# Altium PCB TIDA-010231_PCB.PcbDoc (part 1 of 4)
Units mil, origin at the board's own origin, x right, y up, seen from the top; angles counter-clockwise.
Board outline 3937.01 x 3740.16 mil, 4 copper layers (Top Layer, Signal Layer 1, Signal Layer 2, Bottom Layer), stack 65.355 mil thick; 295 components, 163 nets, 818 pads, 213 vias.
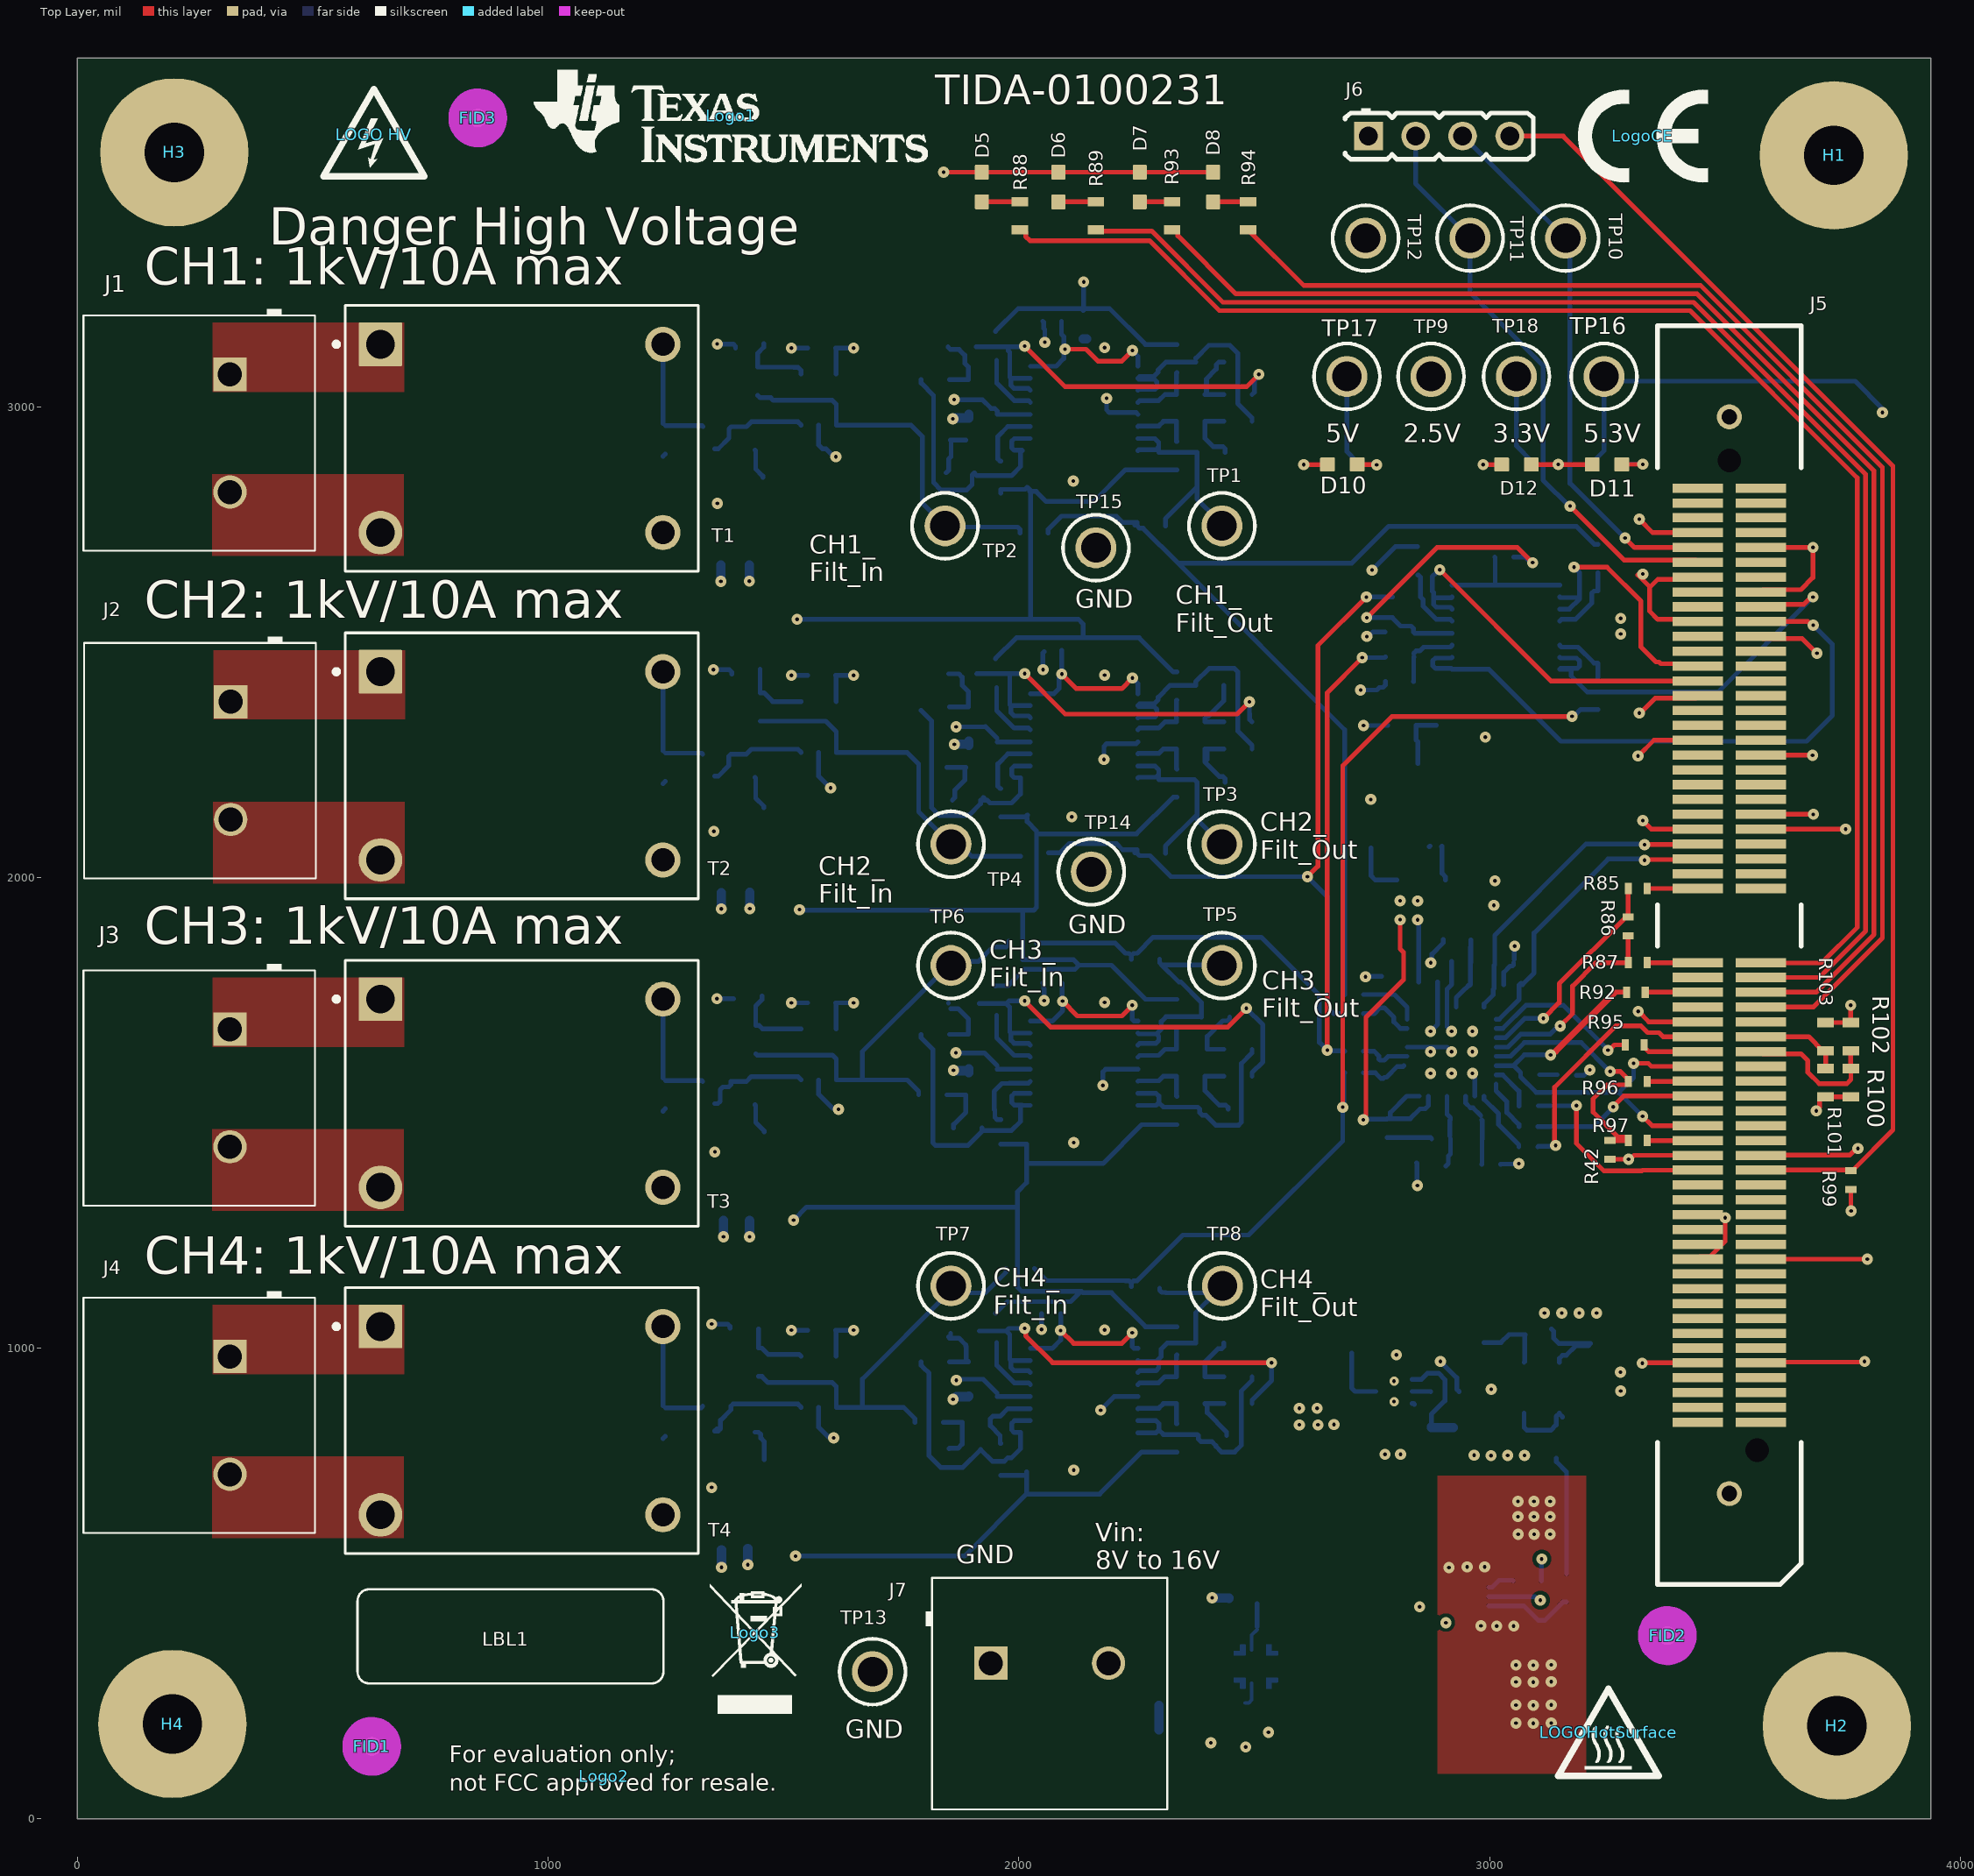
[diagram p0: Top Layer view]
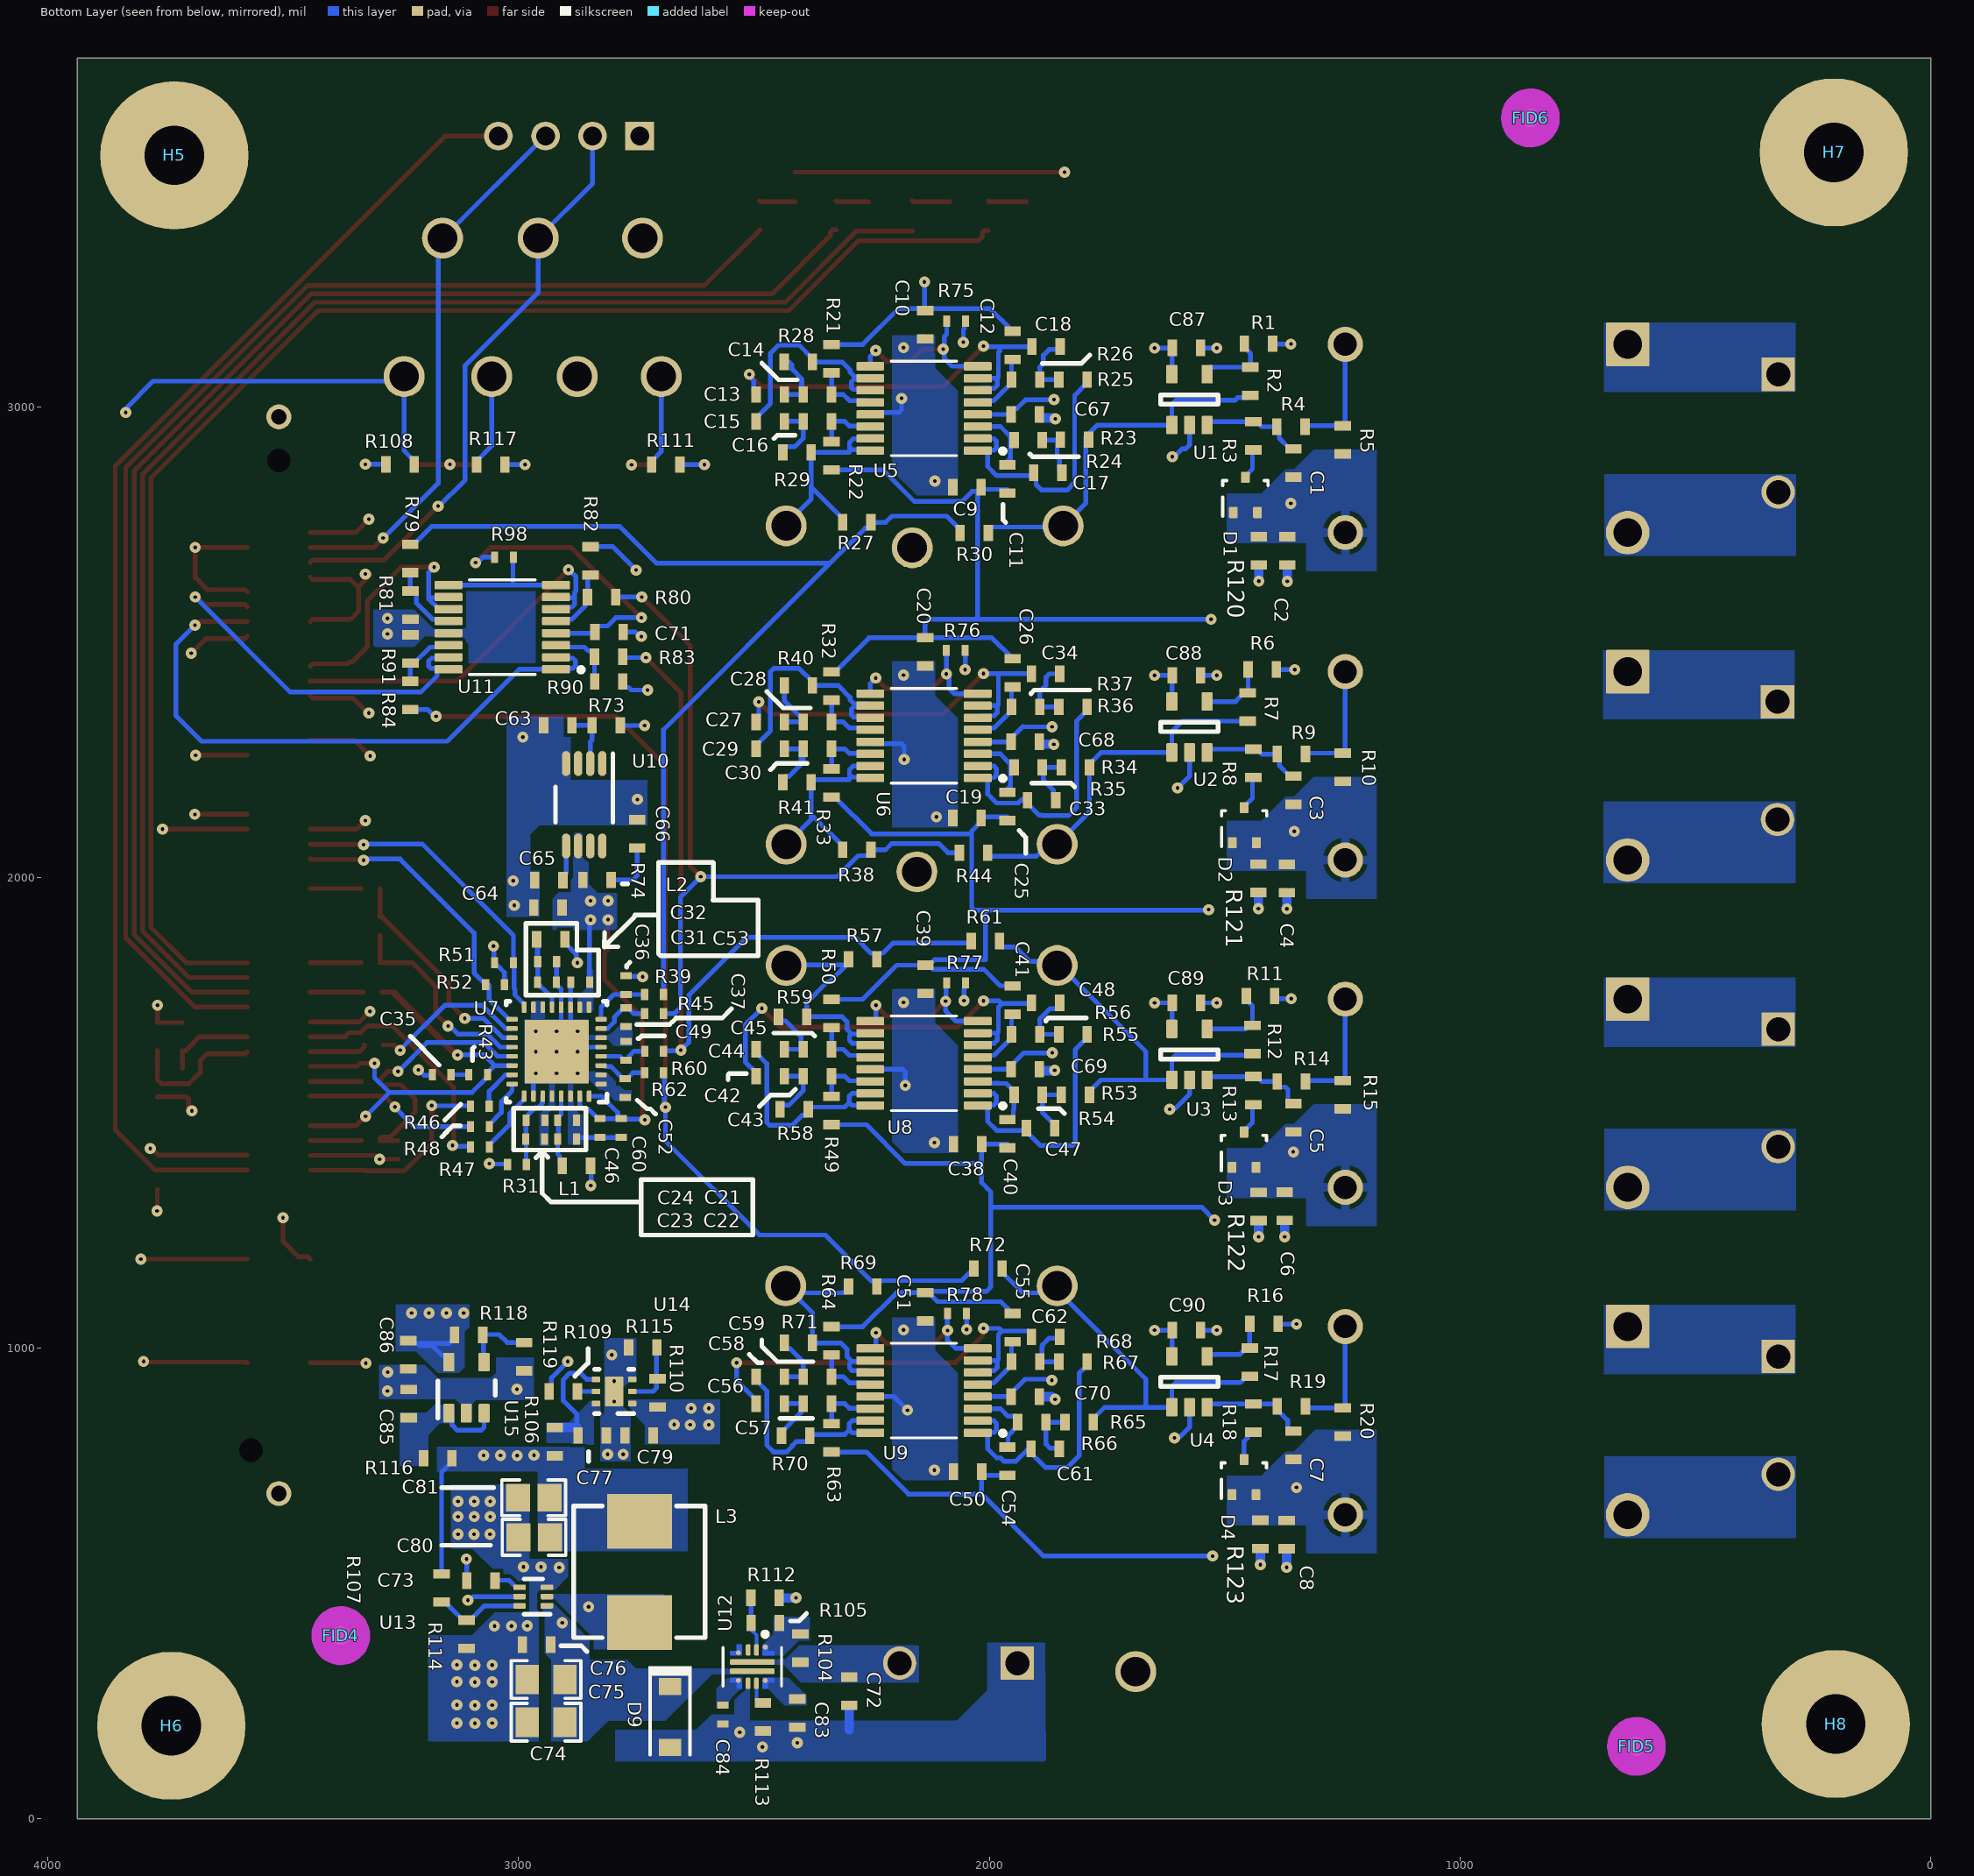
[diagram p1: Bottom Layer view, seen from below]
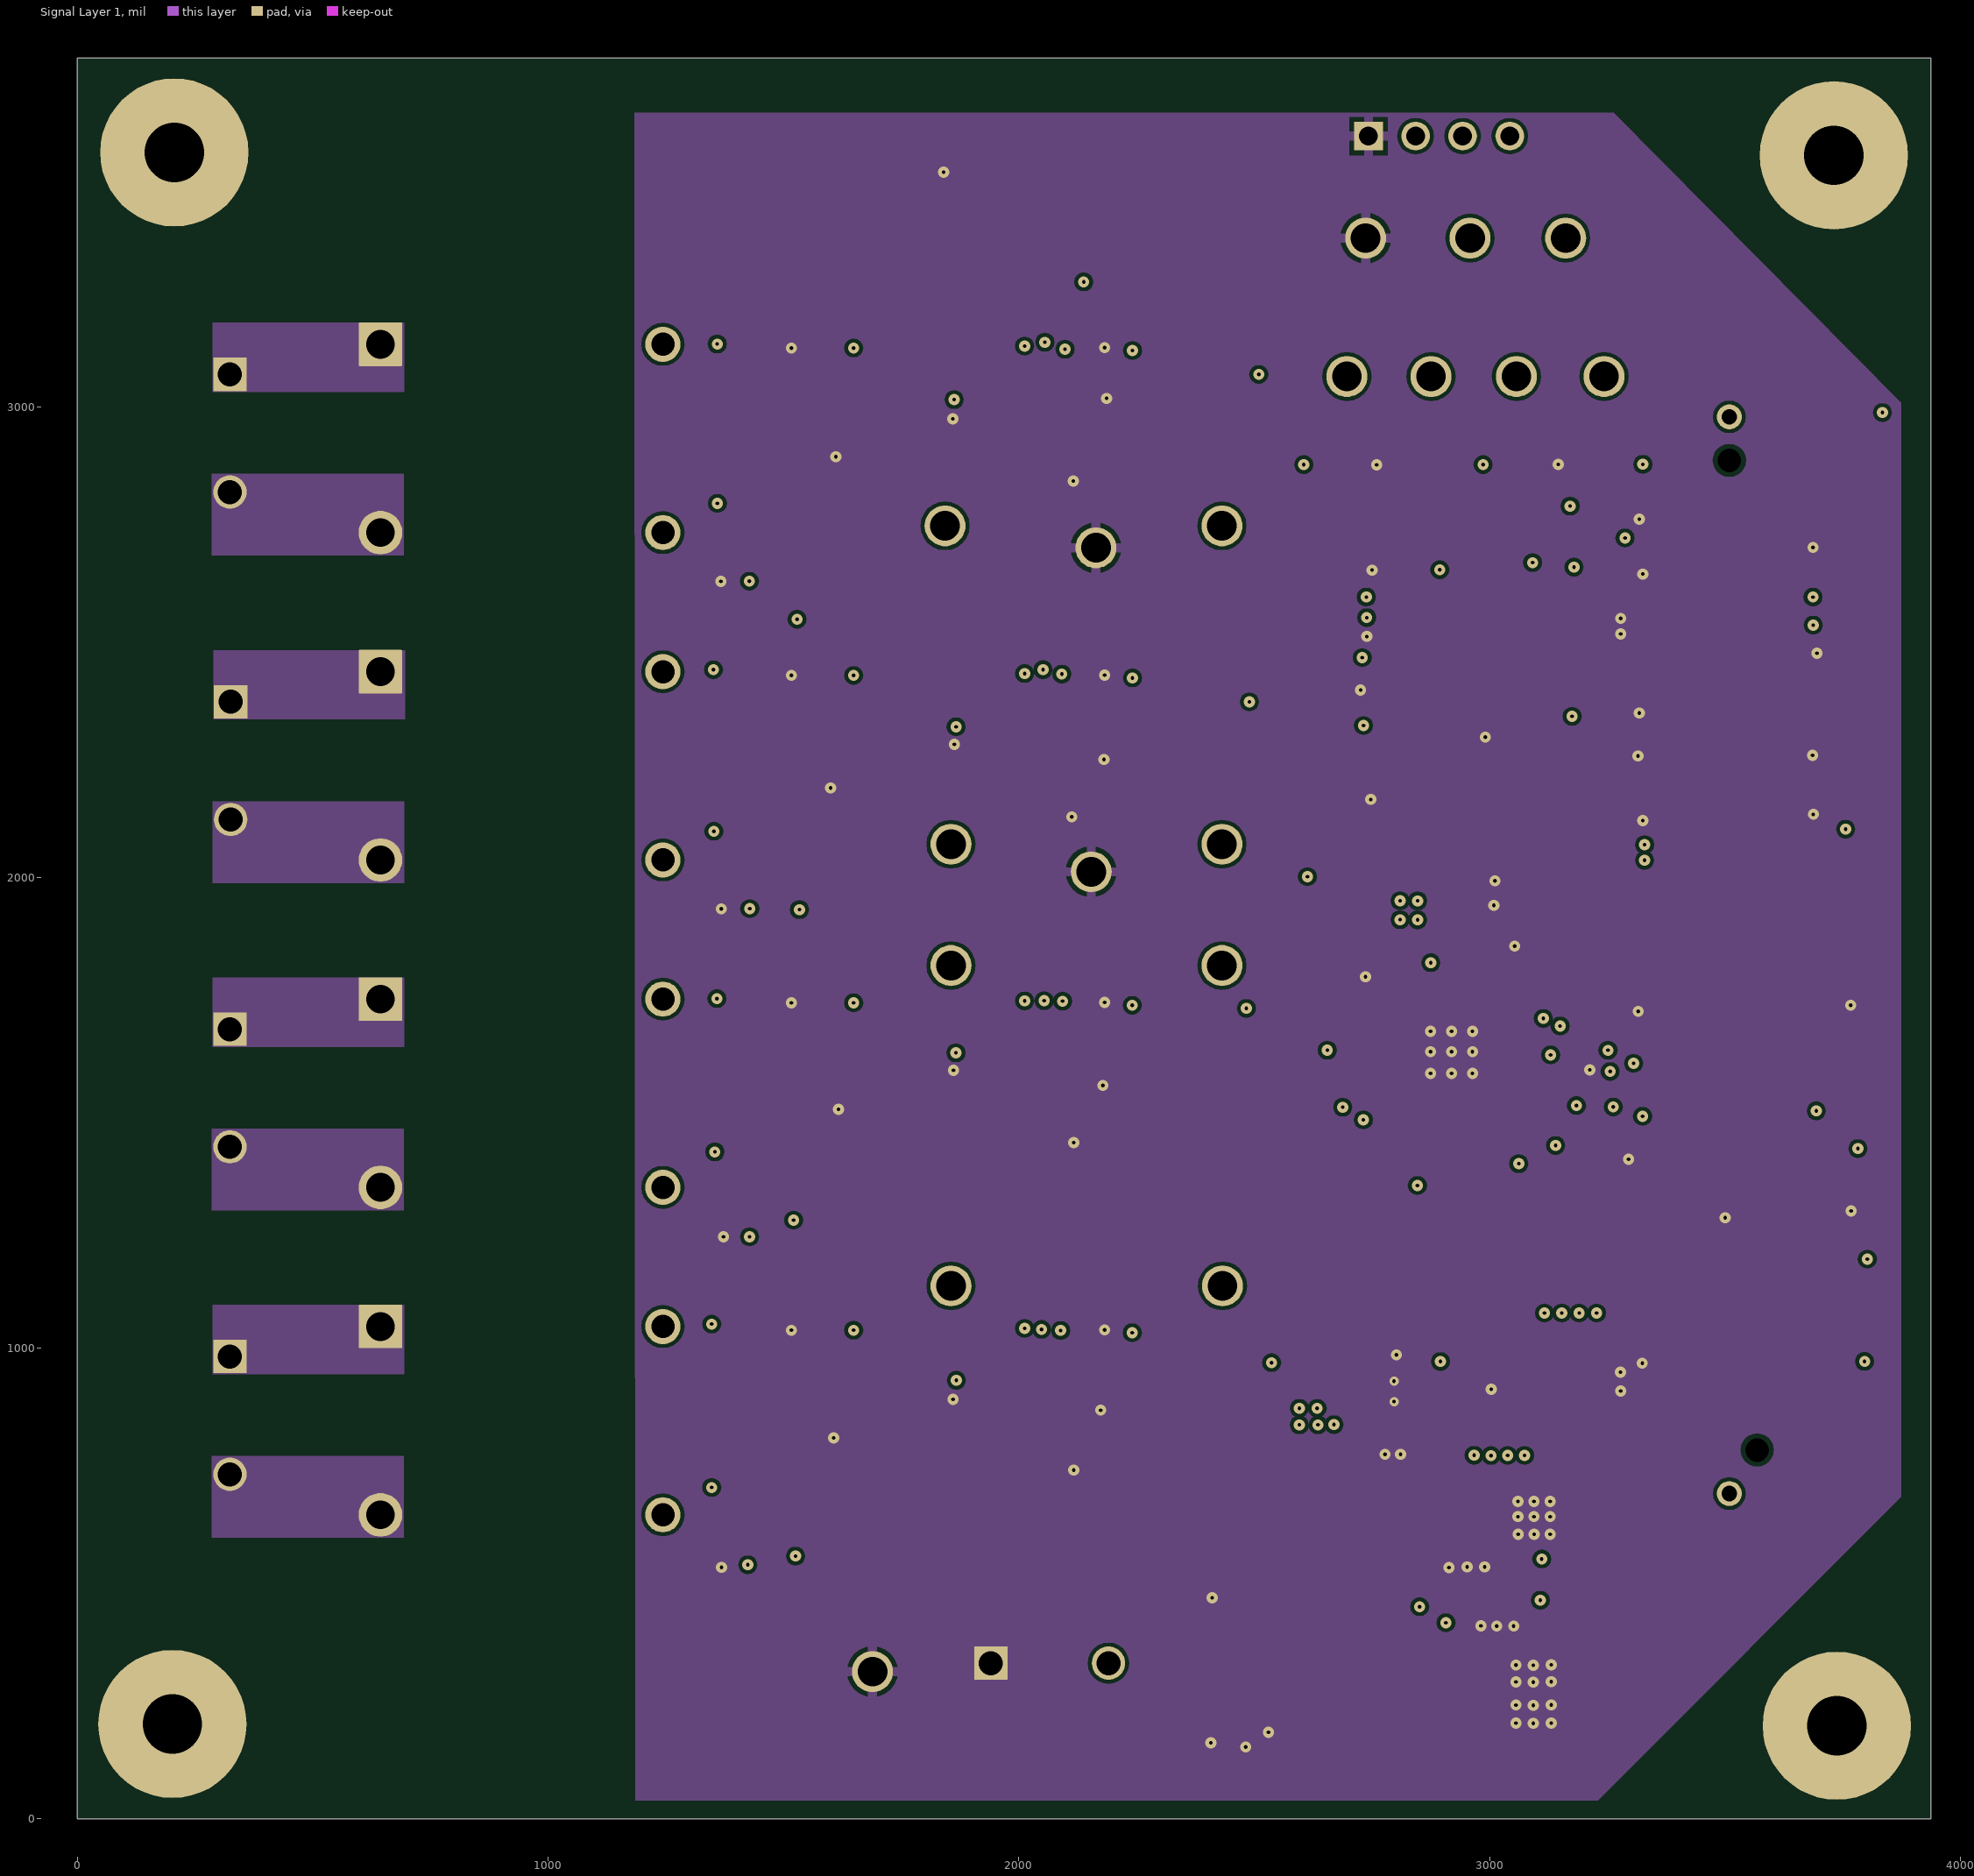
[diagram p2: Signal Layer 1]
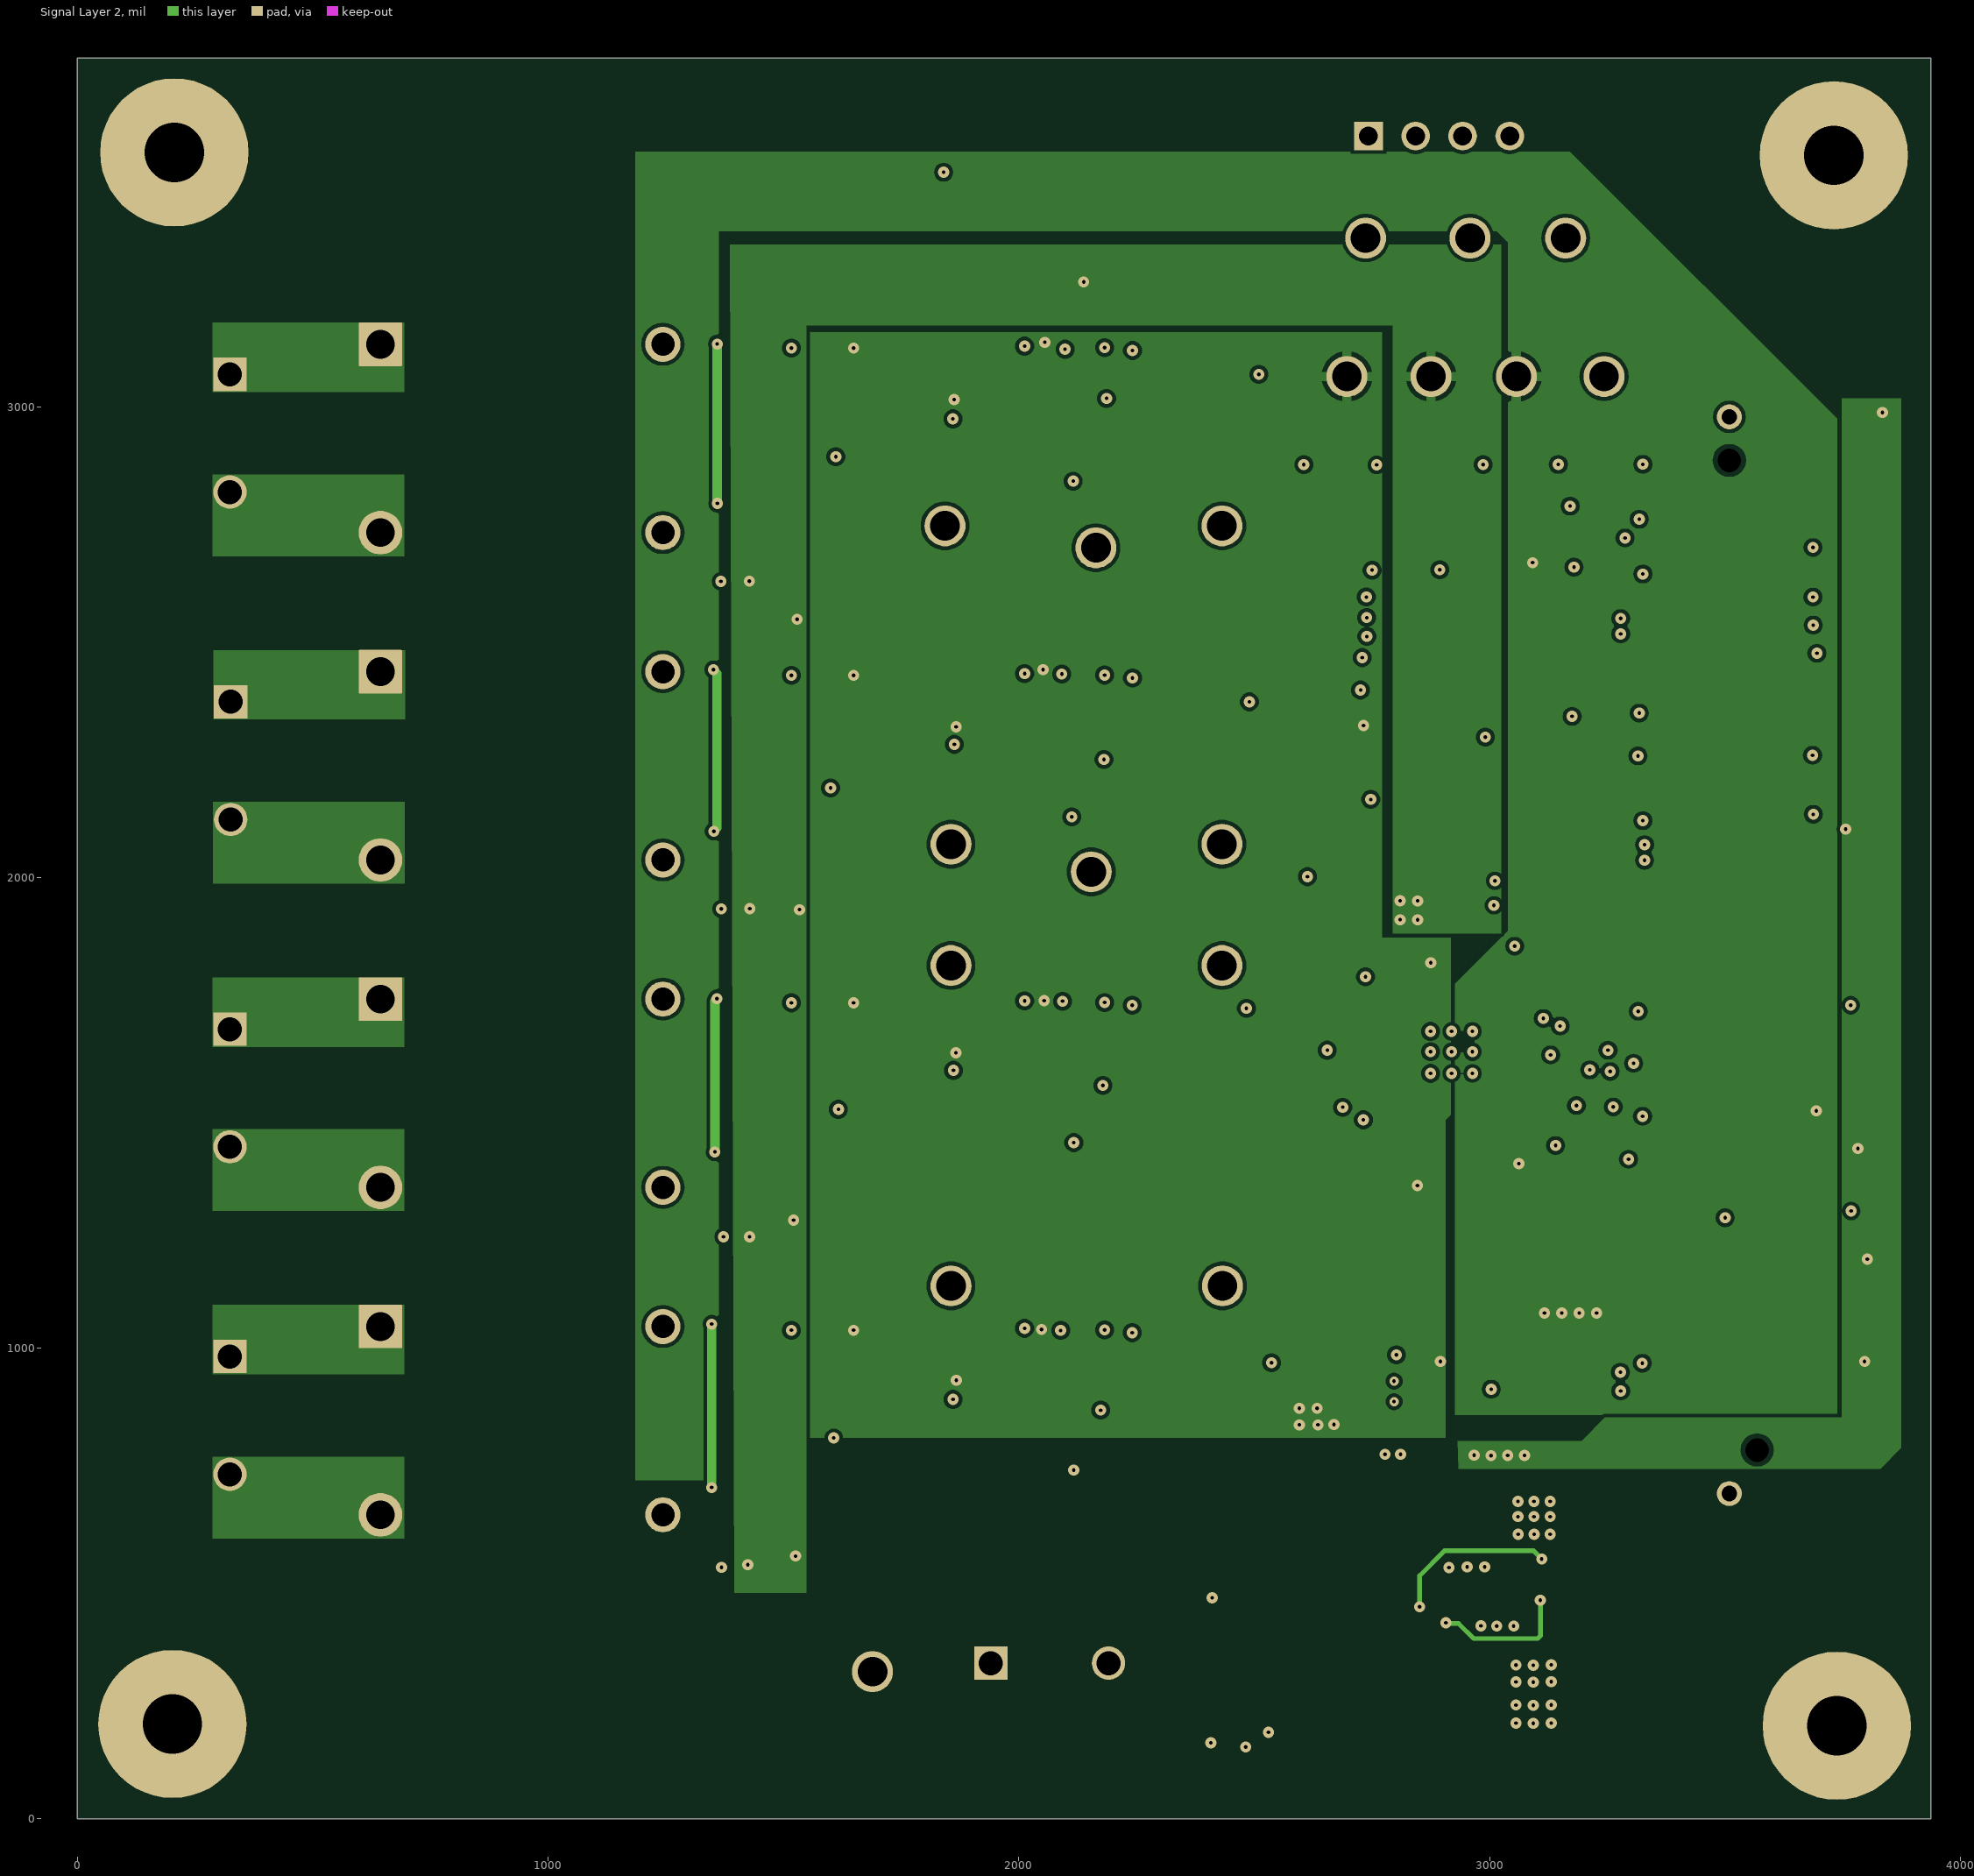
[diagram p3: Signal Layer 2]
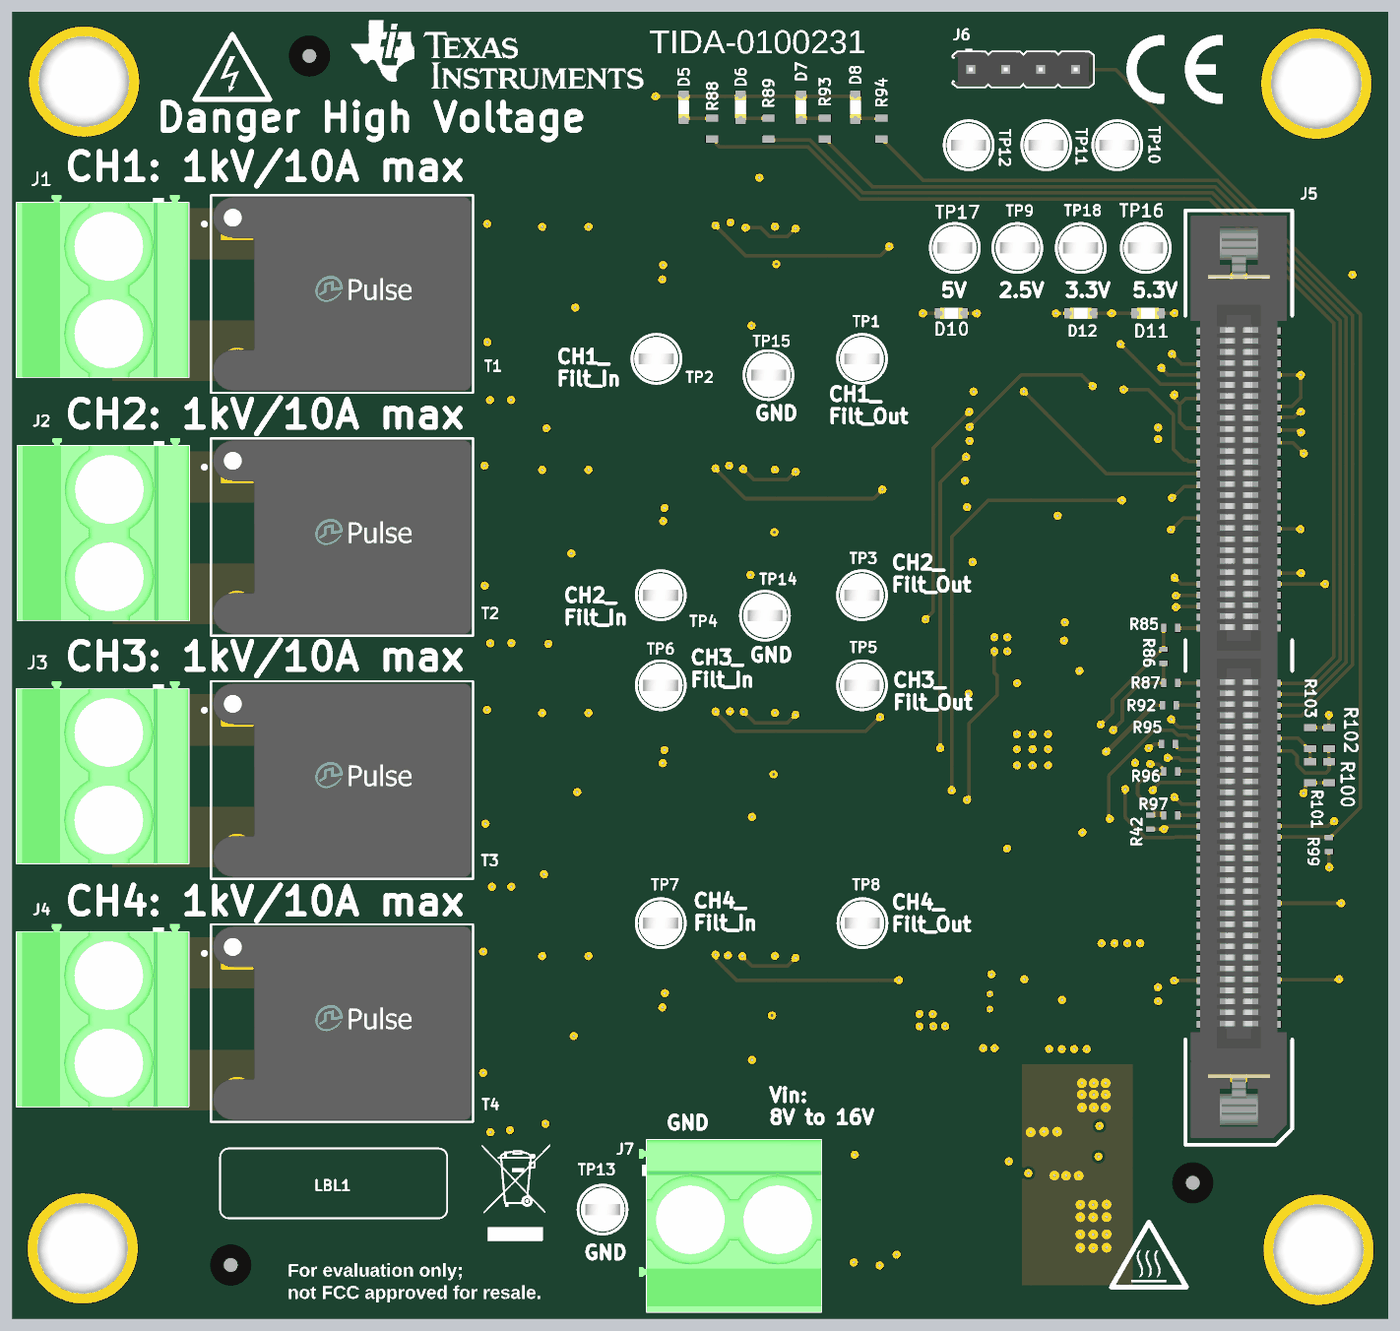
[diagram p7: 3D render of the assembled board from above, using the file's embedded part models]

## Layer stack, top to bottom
Top Solder: solder mask 0.3937, Solder Resist, Dk 3.5
Top Layer: signal copper 1.378
Dielectric 1: prepreg 6.2992, FR-4, Dk 4.2
Signal Layer 1: signal copper 1.378
Dielectric 2: core 47.2441, FR-4, Dk 4.8
Signal Layer 2: signal copper 1.378
Dielectric 3: prepreg 6.2992, FR-4, Dk 4.2
Bottom Layer: signal copper 1.378
Bottom Solder: solder mask 0.3937, Solder Resist, Dk 3.5

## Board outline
0,0 0,3740.16 3937.01,3740.16 3937.01,0

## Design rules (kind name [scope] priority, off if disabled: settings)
AcuteAngle [All] p1: minimum=4.50000000000000E+0001 checktracksonly=FALSE
AssemblyTestPointUsage [All] p1: valid=2
BoardOutlineClearance BoardOutlineClearance_MountingHoles [OnCopper and InComponentClass('Mounting Holes')] p1: gap=39.37 ignorepadtopadclearanceinfootprint=FALSE
BoardOutlineClearance BoardOutlineClearance_Poly [OnCopper and IsPoly] p2: gap=25 ignorepadtopadclearanceinfootprint=FALSE
BoardOutlineClearance [OnCopper and Not InComponentClass('Logo') and not InComponentClass('FiducialMark') and not InRegion(1000,500,4000,800) and not InPoly] p3: gap=75 ignorepadtopadclearanceinfootprint=FALSE
Clearance Clearance_Keepouts [((IsTrack Or IsArc) And Not InPoly) And IsFree and IsKeepOut vs ((IsTrack Or IsArc) And Not InPoly) And IsFree and IsKeepOut] p1: gap=0 ignorepadtopadclearanceinfootprint=FALSE
Clearance Clearance_FiducialMark [IsKeepOut and InComponentClass('FiducialMark') vs IsPad and InComponentClass('FiducialMark')] p2: gap=0 ignorepadtopadclearanceinfootprint=FALSE
Clearance [All] p3: gap=7.87 ignorepadtopadclearanceinfootprint=TRUE except(9.84: Arc-Hole Track-Hole SMDPad-Hole THPad-Hole Via-Hole Fill-Hole Poly-Hole Region-Hole Text-Hole)
ComponentClearance ComponentClearance_MountingHoles_FiducialMarks [InComponentClass('Mounting Holes') vs InComponentClass('FiducialMark')] p1: gap=50 collisioncheckmode=3 verticalgap=10 showdistances=FALSE
ComponentClearance ComponentClearance_Shunt [InComponentClass('Header') vs InComponentClass('Shunt')] p2: gap=0 collisioncheckmode=3 verticalgap=0 showdistances=FALSE
ComponentClearance ComponentClearance_Logo [InComponentClass('Logo')] p3: gap=50 collisioncheckmode=3 verticalgap=10 showdistances=FALSE
ComponentClearance ComponentClearance_ScrewToNut [(HasFootprint('NY PMS 440 0025 PH')) vs (HasFootprint('Keystone_1902C'))] p4: gap=5 collisioncheckmode=3 verticalgap=10 showdistances=FALSE
ComponentClearance ComponentClearance_MountingHoles [InComponentClass('Mounting Holes')] p5: gap=118.11 collisioncheckmode=3 verticalgap=100000 showdistances=FALSE
ComponentClearance ComponentClearance_SmallPassives [HasFootprint('0201*') or HasFootprint('0402*') or HasFootprint('0508') or HasFootprint('0603*') or HasFootprint('0612') or HasFootprint('0805*') or HasFootprint('0815*') or HasFootprint('0830*') or HasFootprint('1206*') or HasFootprint('1210*') or HasFootprint('1808*') or HasFootprint('1812*') or HasFootprint('1825*') or HasFootprint('2010*') or HasFootprint('2220*') or HasFootprint('2225*') or HasFootprint('2512*') or HasFootprint('2728*') or HasFootprint('3518*') vs HasFootprint('0201*') or HasFootprint('0402*') or HasFootprint('0508') or HasFootprint('0603*') or HasFootprint('0612') or HasFootprint('0805*') or HasFootprint('0815*') or HasFootprint('0830*') or HasFootprint('1206*') or HasFootprint('1210*') or HasFootprint('1808*') or HasFootprint('1812*') or HasFootprint('1825*') or HasFootprint('2010*') or HasFootprint('2220*') or HasFootprint('2225*') or HasFootprint('2512*') or HasFootprint('2728*') or HasFootprint('3518*')] p6: gap=14.96 collisioncheckmode=3 verticalgap=10 showdistances=FALSE
ComponentClearance ComponentClearance_THtoSMT [IsThruComponent vs IsSMTComponent] p7: gap=40 collisioncheckmode=3 verticalgap=30 showdistances=FALSE
ComponentClearance ComponentClearance_THtoTH [IsThruComponent vs IsThruComponent] p8: gap=30 collisioncheckmode=3 verticalgap=30 showdistances=FALSE
ComponentClearance [All] p9: gap=30 collisioncheckmode=3 verticalgap=10 showdistances=FALSE
DiffPairsRouting [All] p1: maxlimit=100 minlimit=10 mostfreqgap=10 toplayer_minwidth=15 toplayer_maxwidth=15 toplayer_prefwidth=15 midlayer1_minwidth=15 midlayer1_maxwidth=15 midlayer1_prefwidth=15 midlayer2_minwidth=15 midlayer2_maxwidth=15 midlayer2_prefwidth=15 bottomlayer_minwidth=15 bottomlayer_maxwidth=15 bottomlayer_prefwidth=15 maxuncoupledlength=1000
FabricationTestPointUsage TestPointUsage [All] p1: valid=2 allowmultiple=FALSE
FabricationTestpoint Testpoint [All] p1: side=3 testpointundercomponent=TRUE minsize=40 maxsize=100 preferedsize=60 minholesize=0 maxholesize=40 preferedholesize=32 testpointgrid=1 allowsidetop=TRUE allowsidebottom=TRUE usegrid=TRUE gridtolerance=0.01
FanoutControl Fanout_LCC [IsLCC] p1: bgadir=Out bgaviamode=Centered fanoutstyle=Auto fanoutdirection=Alternating viagrid=1 // Fanout_LCC (Default Rule)
FanoutControl Fanout_BGA [IsBGA] p2: bgadir=Out bgaviamode=Centered fanoutstyle=Auto fanoutdirection=Alternating viagrid=1 // Fanout_BGA (Default Rule)
FanoutControl Fanout_Default [All] p4: bgadir=Out bgaviamode=Centered fanoutstyle=Auto fanoutdirection=Alternating viagrid=1 // Fanout_Default (Default Rule)
FanoutControl Fanout_Small [(CompPinCount < 5)] p5: bgadir=Out bgaviamode=Centered fanoutstyle=Auto fanoutdirection=OutThenIn viagrid=1 // Fanout_Small (Default Rule)
HoleSize [All] p1: absolutevalues=TRUE maxlimit=251 minlimit=7.87 maxpercent=80.000 minpercent=20.000
MinimumAnnularRing MinimumAnnularRing_ThermalPadVias [IsVia and InAnyComponent] p1: minimumring=5.91
MinimumAnnularRing [All] p2: minimumring=5.91
MinimumSolderMaskSliver MinimumSolderMaskSliver_Logo [InComponentClass('Logo') vs InComponentClass('Logo')] p1: minsoldermaskwidth=0.7
MinimumSolderMaskSliver [All] p2: minsoldermaskwidth=3.94
PlaneConnect [All] p1: planeconnectstyle=Relief reliefexpansion=10 reliefentries=4 reliefconductorwidth=10 reliefairgap=10
PolygonConnect PolygonConnectHighCurrent [InNetClass('HighCurrent')] p1: connectstyle=Direct reliefconductorwidth=20 reliefentries=4 polygonreliefangle="90 Angle" airgapwidth=10
PolygonConnect PolygonConnectStandard [All] p2: thpad.connectstyle=Relief thpad.reliefconductorwidth=20 thpad.reliefentries=4 thpad.polygonreliefangle="90 Angle" thpad.airgapwidth=10 smdpad.connectstyle=Direct smdpad.reliefconductorwidth=10 smdpad.reliefentries=4 smdpad.polygonreliefangle="90 Angle" smdpad.airgapwidth=10 via.connectstyle=Direct via.reliefconductorwidth=10 via.reliefentries=4 via.polygonreliefangle="90 Angle" via.airgapwidth=10
RoutingVias ThermalPadVias [IsVia and InAnyComponent] p1: holewidth=7.87 width=19.68 viastyle="Through Hole" minholewidth=7.87 minwidth=19.68 maxholewidth=12.99 maxwidth=23.62
RoutingVias [All] p2: holewidth=16 width=34 viastyle="Through Hole" minholewidth=7.87 minwidth=19.68 maxholewidth=40 maxwidth=65
SilkToBoardRegionClearance [Not ((IsComment or IsDesignator) And (Hide <> 'False')) and not InRegion(1000,500,4000,800)] p1:
SilkToSilkClearance SilkToSilkClearance_Pb-FreeLogo [(HasFootprint('Pb-Free_Overlay_Medium') OR HasFootprint('Pb-Free_Overlay_Small')) vs (HasFootprint('Pb-Free_Overlay_Medium') OR HasFootprint('Pb-Free_Overlay_Small'))] p1: silktosilkclearance=0
SilkToSilkClearance [All] p2: silktosilkclearance=3.94
SilkToSolderMaskClearance SilkToComponentPadClearance [(IsPad or IsFill or IsRegion) and InAnycomponent] p1: minsilkscreentomaskgap=3.54 clearancetoexposedcopper=TRUE
SilkToSolderMaskClearance "Silk to Solder Mask Opening" [All] p2: minsilkscreentomaskgap=3.54 clearancetoexposedcopper=FALSE
SolderMaskExpansion [All] p1: expansion=1.97 istentingtop=FALSE
UnRoutedNet [All] p1: checkbadconnections=TRUE
Width [All] p1: maxlimit=20 minlimit=7.87 preferedwidth=10 checkconnectedcopper=TRUE
14 further rules are at their usual default settings.

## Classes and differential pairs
net class HighCurrent: CH1+ CH1- CH2+ CH2- CH3+ CH3- CH4+ CH4-
component class FiducialMark: FID1 FID2 FID3 FID4 FID5 FID6
component class Header: J6
component class TIDA-010231_Power: C72 C73 C74 C75 C76 C77 C79 C80 C81 C83 C84 C85 C86 D9 D10 D11 D12 J7 L3 R104 R105 R106 R107 R108 R109 R110 R111 R112 R113 R114 R115 R116 R117 R118 R119 TP16 TP17 TP18 U12 U13 U14 U15
component class TIDA-010231_Interface: C71 D5 D6 D7 D8 J5 J6 R79 R80 R81 R82 R83 R84 R85 R86 R87 R88 R89 R90 R91 R92 R93 R94 R95 R96 R97 R98 R99 R100 R101 R102 R103 TP10 TP11 TP12 TP13 TP14 TP15 U11
component class TIDA-010231_Filter_and_ADC: C9 C10 C11 C12 C13 C14 C15 C16 C17 C18 C19 C20 C21 C22 C23 C24 C25 C26 C27 C28 C29 C30 C31 C32 C33 C34 C35 C36 C37 C38 C39 C40 C41 C42 C43 C44 C45 C46 C47 C48 C49 C50 C51 C52 C53 C54 C55 C56 C57 C58 C59 C60 C61 C62 C63 C64 C65 C66 C67 C68 C69 C70 L1 L2 R21 R22 R23 R24 R25 R26 R27 R28 R29 R30 R31 R32 R33 R34 R35 R36 R37 R38 R39 R40 R41 R42 R43 R44 R45 R46 R47 R48 R49 R50 R51 R52 R53 R54 R55 R56 R57 R58 R59 R60 R61 R62 R63 R64 R65 R66 R67 R68 R69 R70 R71 R72 R73 R74 R75 R76 R77 R78 TP1 TP2 TP3 TP4 TP5 TP6 TP7 TP8 TP9 U5 U6 U7 U8 U9 U10
component class TIDA-010231_Current_Transformer: C1 C2 C3 C4 C5 C6 C7 C8 C87 C88 C89 C90 D1 D2 D3 D4 J1 J2 J3 J4 R1 R2 R3 R4 R5 R6 R7 R8 R9 R10 R11 R12 R13 R14 R15 R16 R17 R18 R19 R20 R120 R121 R122 R123 T1 T2 T3 T4 U1 U2 U3 U4
component class "Mounting Holes": H1 H2 H3 H4
component class Logo: Logo1
component class TIDA-010231_Hardware: FID1 FID2 FID3 FID4 FID5 FID6 H1 H2 H3 H4 H5 H6 H7 H8 LBL1 Logo1 Logo2 Logo3 Logo4 "LOGO HV" LogoCE LOGOHotSurface ZZ1 ZZ2 ZZ3 ZZ4
component class AssemblyNote: ZZ1 ZZ2 ZZ3 ZZ4
component class Label: LBL1

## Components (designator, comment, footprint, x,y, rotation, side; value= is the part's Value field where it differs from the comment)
C1 "C0603C222K5RACTU" 0603S 1353.67,2880.42 r270 bottom value=2200pF
C2 "C0603C104K5RACAUTO" 0603S 1366.65,2693.69 r270 bottom value=0.1uF
C3 "C0603C222K5RACTU" 0603S 1353.67,2184.91 r270 bottom value=2200pF
C4 "C0603C104K5RACAUTO" 0603S 1367.61,1997.76 r270 bottom value=0.1uF
C5 "C0603C222K5RACTU" 0603S 1353.67,1489.4 r270 bottom value=2200pF
C6 "C0603C104K5RACAUTO" 0603S 1372.28,1301.38 r270 bottom value=0.1uF
C7 "C0603C222K5RACTU" 0603S 1353.67,793.89 r270 bottom value=2200pF
C8 "C0603C104K5RACAUTO" 0603S 1368.29,603.72 r270 bottom value=0.1uF
C9 "C0603C104K5RACAUTO" 0603S 2047.47,2828.72 r0 bottom value=0.1uF
C10 "C0603C104K5RACAUTO" 0603S 2136.3,3173.91 r270 bottom value=0.1uF
C11 "06033C101KAT2A" 0603S 1961.35,2846.33 r90 bottom value=100pF
C12 "06033C101KAT2A" 0603S 1950.28,3130.13 r270 bottom value=100pF
C13 "GRM1885C1E132JA01D" 0603S 2465.39,3025.77 r0 bottom value=1300pF
C14 "GRM188R71H102KA01D" 0603S 2365,3025.77 r0 bottom value=1000pF
C15 "GRM1885C1H392JA01D" 0603S 2465.39,2968.68 r0 bottom value=3900pF
C16 "C0603X222K5RACTU" 0603S 2365,2968.68 r0 bottom value=2200pF
C17 "GRM1885C1H151JA01D" 0603S 1875.51,2859.65 r0 bottom value=150pF
C18 "06035A331JAT2A" 0603S 1879.45,3127.55 r0 bottom value=330pF
C19 "C0603C104K5RACAUTO" 0603S 2047.47,2126.02 r0 bottom value=0.1uF
C20 "C0603C104K5RACAUTO" 0603S 2136.3,2479.16 r270 bottom value=0.1uF
C21 "GRM155R71C102KA01D" 0402S 2896.89,1484.25 r180 bottom value=1000pF
C22 "GRM155R70J105MA12D" 0402S 2896.89,1444.39 r180 bottom value=1uF
C23 "GRM155R70J105MA12D" 0402S 2964.45,1444.39 r180 bottom value=1uF
C24 "GRM155R71C102KA01D" 0402S 2963.66,1484.25 r180 bottom value=1000pF
C25 "06033C101KAT2A" 0603S 1961.35,2150.81 r90 bottom value=100pF
C26 "06033C101KAT2A" 0603S 1950.28,2434.62 r270 bottom value=100pF
C27 "GRM1885C1E132JA01D" 0603S 2465.39,2330.26 r0 bottom value=1300pF
C28 "GRM188R71H102KA01D" 0603S 2365,2330.26 r0 bottom value=1000pF
C29 "GRM1885C1H392JA01D" 0603S 2465.39,2273.17 r0 bottom value=3900pF
C30 "C0603X222K5RACTU" 0603S 2365,2273.17 r0 bottom value=2200pF
C31 "GRM155R71C102KA01D" 0402S 2939.5,1777.18 r180 bottom value=1000pF
C32 "GRM155R70J105MA12D" 0402S 2939.25,1821.22 r180 bottom value=1uF
C33 "GRM1885C1H151JA01D" 0603S 1888.68,2164.08 r0 bottom value=150pF
C34 "06035A331JAT2A" 0603S 1880.35,2432.39 r0 bottom value=330pF
C35 "C0402C101J3GACTU" 0402S 3163.48,1580.76 r180 bottom value=100pF
C36 "GRM155R71H152JA01D" 0402S 2771.65,1771.27 r90 bottom value=1500pF
C37 "GRM155R71H152JA01D" 0402S 2771.65,1702.84 r270 bottom value=1500pF
C38 "C0603C104K5RACAUTO" 0603S 2046.14,1433.18 r0 bottom value=0.1uF
C39 "C0603C104K5RACAUTO" 0603S 2135.55,1783.47 r270 bottom value=0.1uF
C40 "06033C101KAT2A" 0603S 1961.35,1455.3 r90 bottom value=100pF
C41 "06033C101KAT2A" 0603S 1950.28,1739.11 r270 bottom value=100pF
C42 "GRM1885C1E132JA01D" 0603S 2465.39,1577.66 r0 bottom value=1300pF
C43 "GRM188R71H102KA01D" 0603S 2365,1577.66 r0 bottom value=1000pF
C44 "GRM1885C1H392JA01D" 0603S 2465.39,1634.74 r0 bottom value=3900pF
C45 "C0603X222K5RACTU" 0603S 2365,1634.74 r0 bottom value=2200pF
C46 "GRM155R61A106ME11" 0402S 2827.02,1467.52 r270 bottom value=10uF
C47 "GRM1885C1H151JA01D" 0603S 1891.17,1467.52 r0 bottom value=150pF
C48 "06035A331JAT2A" 0603S 1880.35,1733.58 r0 bottom value=330pF
C49 "GRM155R71H152JA01D" 0402S 2771.65,1631.5 r90 bottom value=1500pF
C50 "C0603C104K5RACAUTO" 0603S 2046.14,737.66 r0 bottom value=0.1uF
C51 "C0603C104K5RACAUTO" 0603S 2136.24,1087.63 r270 bottom value=0.1uF
C52 "GRM155R71H152JA01D" 0402S 2773.84,1552.83 r270 bottom value=1500pF
C53 "GRM155R60J226ME11D" 0402S 2869.33,1777.18 r180 bottom value=22uF
C54 "06033C101KAT2A" 0603S 1961.35,759.79 r90 bottom value=100pF
C55 "06033C101KAT2A" 0603S 1950.28,1043.6 r270 bottom value=100pF
C56 "GRM1885C1E132JA01D" 0603S 2465.39,882.15 r0 bottom value=1300pF
C57 "GRM188R71H102KA01D" 0603S 2365,882.15 r0 bottom value=1000pF
C58 "GRM1885C1H392JA01D" 0603S 2465.39,939.23 r0 bottom value=3900pF
C59 "C0603X222K5RACTU" 0603S 2365,939.23 r0 bottom value=2200pF
C60 "GRM155R61A106ME11" 0402S 2782.14,1467.52 r270 bottom value=10uF
C61 "GRM1885C1H151JA01D" 0603S 1881.42,786.29 r0 bottom value=150pF
C62 "06035A331JAT2A" 0603S 1880.35,1023.91 r0 bottom value=330pF
C63 "GRM188Z71A106MA73D" 0603S 2916.58,2322.92 r0 bottom value=10uF
C64 "CGA3E1X7R1E105K080AC" 0603S 2937.72,1935.94 r0 bottom value=1uF
C65 "CGA3E1X7R1E105K080AC" 0603S 2935.94,1994.07 r0 bottom value=1uF
C66 "GRM188R60J476ME15D" 0603S 2748.04,2092.37 r90 bottom value=47uF
C67 "C0603C104K5RACAUTO" 0603S 1923.66,2983.54 r180 bottom value=0.1uF
C68 "C0603C104K5RACAUTO" 0603S 1923.66,2288.03 r180 bottom value=0.1uF
C69 "C0603C104K5RACAUTO" 0603S 1923.66,1592.52 r180 bottom value=0.1uF
C70 "C0603C104K5RACAUTO" 0603S 1923.66,897.01 r180 bottom value=0.1uF
C71 "C0603C104K5RACAUTO" 0603S 2807.97,2521.46 r180 bottom value=0.1uF
C72 "C1608X5R1H105K080AB" 0603S 2297.65,271.3 r270 bottom value=1uF
C73 "C0603C104J3RACTU" 0603S 3080.09,505.66 r0 bottom value=0.1uF
C74 "GRM219R61E106MA12" 0805_HV 2941.5,205.1 r0 bottom value=10uF
C75 "GRM219R61E106MA12" 0805_HV 2941.5,295.99 r0 bottom value=10uF
C76 "C0603C104J3RACTU" 0603S 2961.65,370.17 r0 bottom value=0.1uF
C77 "GRM188Z71A475ME15D" 0603S 2843.43,814.53 r180 bottom value=4.7uF
C79 "GRM188R60J476ME15D" 0603S 2743.84,814.53 r0 bottom value=47uF
C80 "GRM21BR61A226ME44L" 0805 2967.08,597.95 r180 bottom value=22uF
C81 "GRM21BR61A226ME44L" 0805 2967.92,682.05 r0 bottom value=22uF
C83 "C0603C104J3RACTU" 0603S 2407.9,224.47 r270 bottom value=0.1uF
C84 "GRM1555C1H102FA01D" 0402S 2565.86,221.76 r270 bottom value=1000pF
C85 "CGA3E1X7R1E105K080AC" 0603S 3233.26,882.15 r90 bottom value=1uF
C86 "CGA3E1X7R1E105K080AC" 0603S 3234.35,985.7 r270 bottom value=1uF
C87 "C0603C104K5RACAUTO" 0603S 1580.98,3124.64 r180 bottom value=0.1uF
C88 "C0603C104K5RACAUTO" 0603S 1580.98,2429.13 r180 bottom value=0.1uF
C89 "C0603C104K5RACAUTO" 0603S 1580.98,1733.62 r180 bottom value=0.1uF
C90 "C0603C104K5RACAUTO" 0603S 1580.98,1038.11 r180 bottom value=0.1uF
D1 "BAV99W-7-F" SOT-323 1455.85,2812.47 r90 bottom value=75V
D2 "BAV99W-7-F" SOT-323 1458.35,2110.91 r90 bottom value=75V
D3 "BAV99W-7-F" SOT-323 1458.79,1421.44 r90 bottom value=75V
D4 "BAV99W-7-F" SOT-323 1458.79,725.93 r90 bottom value=75V
D5 "150060VS55040" WL-SMCD-0603 1921.29,3466.54 r270 top value=Green
D6 "150060VS55040" WL-SMCD-0603 2083.96,3466.54 r270 top value=Green
D7 "150060VS55040" WL-SMCD-0603 2256.73,3466.54 r270 top value=Green
D8 "150060VS55040" WL-SMCD-0603 2412.57,3466.54 r270 top value=Green
D9 "DDZ17-7" SOD-123 2678.22,216.37 r270 bottom value=17V
D10 "150060VS55040" WL-SMCD-0603 2687.06,2877.17 r180 top value=Green
D11 "150060VS55040" WL-SMCD-0603 3249.43,2877.17 r0 top value=Green
D12 "150060VS55040" WL-SMCD-0603 3057.06,2877.17 r180 top value=Green
FID1 "Fiducial" Fiducial10-30 625.2,154.02 r0 top
FID2 "Fiducial" Fiducial10-30 3377.68,389.24 r90 top
FID3 "Fiducial" Fiducial10-30 850.39,3613.45 r90 top
FID4 "Fiducial" Fiducial10-30 3377.68,389.24 r90 bottom
FID5 "Fiducial" Fiducial10-30 625.2,154.02 r90 bottom
FID6 "Fiducial" Fiducial10-30 850.39,3613.45 r90 bottom
H1 "NY PMS 440 0025 PH" "NY PMS 440 0025 PH" 3731.27,3534.01 r0 top locked
H2 "NY PMS 440 0025 PH" "NY PMS 440 0025 PH" 3737.66,197.71 r0 top locked
H3 "NY PMS 440 0025 PH" "NY PMS 440 0025 PH" 205.63,3540.1 r0 top locked
H4 "NY PMS 440 0025 PH" "NY PMS 440 0025 PH" 201.69,201.52 r0 top locked
H5 "1902C" Keystone_1902C 3731.27,3534.01 r180 bottom locked
H6 "1902C" Keystone_1902C 3737.66,197.71 r180 bottom locked
H7 "1902C" Keystone_1902C 205.63,3540.1 r180 bottom locked
H8 "1902C" Keystone_1902C 201.69,201.52 r180 bottom locked
J1 "1714955" Phoenix_1714955 323.74,2943.64 r270 top
J2 "1714955" Phoenix_1714955 325.36,2248.11 r270 top
J3 "1714955" Phoenix_1714955 323.74,1552.57 r270 top
J4 "1714955" Phoenix_1714955 323.74,857.03 r270 top
J5 "HSEC8-160-01-L-DV-A-BL" controlCARD-120HSEC 3508.49,1907.29 r270 top
J6 "22284043" Molex_0022284043 2892.75,3574.8 r0 top
J7 "1714955" Phoenix_1714955 2065.3,330.77 r0 top
L1 "742792645" 0603S 2877.23,1387.03 r180 bottom value="470 ohm"
L2 "742792645" 0603S 2931.57,1868.51 r180 bottom value="470 ohm"
L3 "74437349047" WE-LHMI_7050 2743.18,524.65 r90 bottom value=4.7uH
LBL1 "THT-14-423-10" Label_650x200 919.83,387.65 r0 top
Logo1 "Texas Instruments" TI_Stacked_Overlay_Small 1388.16,3617.32 r0 top
Logo2 "FCC disclaimer" FCC_disclaimer 1118.11,90.55 r0 top
Logo3 "WEEE logo" WEEE_Minimum 1439.11,395.22 r0 top
"LOGO HV" "DANGER HIGH VOLTAGE" IEC_HighVoltage_Small 629.92,3577.34 r0 top
LogoCE "CE Mark" CE_Mark_5mm 3325.46,3574.8 r0 top
LOGOHotSurface "CAUTION HOT SURFACE" IEC_HotSurface_Small 3252.16,183.97 r0 top
R1 "CRCW06031K00FKEA" 0603S 1427.97,3133.87 r0 bottom value=1.00k
R2 "CRCW06039K09FKEA" 0603S 1445.28,3053.94 r270 bottom value=9.09k
R3 "CRCW060349R9FKEA" 0603S 1439.08,2937.95 r90 bottom value=49.9
R4 "CRCW0603100RFKEA" 0603S 1359.08,2957.48 r0 bottom value=100
R5 "RG1608P-201-B-T5" 0603S 1248.99,2929.45 r90 bottom value=200
R6 "CRCW06031K00FKEA" 0603S 1420.05,2441.97 r0 bottom value=1.00k
R7 "CRCW06039K09FKEA" 0603S 1450.81,2362.04 r270 bottom value=9.09k
R8 "CRCW060349R9FKEA" 0603S 1439.08,2242.44 r90 bottom value=49.9
R9 "CRCW0603100RFKEA" 0603S 1358.23,2261.94 r0 bottom value=100
R10 "RG1608P-201-B-T5" 0603S 1248.99,2233.93 r90 bottom value=200
R11 "CRCW06031K00FKEA" 0603S 1423.97,1747.78 r0 bottom value=1.00k
R12 "CRCW06039K09FKEA" 0603S 1440.7,1655.41 r270 bottom value=9.09k
R13 "CRCW060349R9FKEA" 0603S 1439.08,1546.92 r90 bottom value=49.9
R14 "CRCW0603100RFKEA" 0603S 1358.23,1566.41 r0 bottom value=100
R15 "RG1608P-201-B-T5" 0603S 1248.99,1538.42 r90 bottom value=200
R16 "CRCW06031K00FKEA" 0603S 1416.28,1051.91 r0 bottom value=1.00k
R17 "CRCW06039K09FKEA" 0603S 1446.6,969.99 r270 bottom value=9.09k
R18 "CRCW060349R9FKEA" 0603S 1439.08,851.41 r90 bottom value=49.9
R19 "CRCW0603100RFKEA" 0603S 1358.23,876.45 r0 bottom value=100
R20 "RG1608P-201-B-T5" 0603S 1248.99,842.91 r90 bottom value=200
R21 "RC0603JR-075K1L" 0603S 2335.47,3102.07 r90 bottom value=5.1k
R22 "RC0603JR-075K1L" 0603S 2335.47,2895.87 r270 bottom value=5.1k
R23 "RC0603JR-075K1L" 0603S 1818.77,2929.81 r0 bottom value=5.1k
R24 "ERJ3EKF1602V" 0603S 1917.32,2929.13 r0 bottom value=16.0k
R25 "CRCW06033K30FKEA" 0603S 1822.36,3057.56 r0 bottom value=3.30k
R26 "RC0603FR-079K1L" 0603S 1922.76,3057.56 r0 bottom value=9.10k
R27 "RMCF0603ZT0R00" 0603S 2281.38,2754.29 r180 bottom value=0
R28 "CRCW06034K30JNEA" 0603S 2405.82,3095.19 r0 bottom value=4.3k
R29 "CRCW0603680RJNEA" 0603S 2408.31,2902.83 r0 bottom value=680
R30 "RMCF0603ZT0R00" 0603S 2032.2,2731.75 r180 bottom value=0
R31 "CRCW04020000Z0ED" 0402S 3003.44,1390.22 r0 bottom value=0
R32 "RC0603JR-075K1L" 0603S 2335.47,2406.56 r90 bottom value=5.1k
R33 "RC0603JR-075K1L" 0603S 2335.47,2200.35 r270 bottom value=5.1k
R34 "RC0603JR-075K1L" 0603S 1816.93,2233.62 r0 bottom value=5.1k
R35 "ERJ3EKF1602V" 0603S 1917.32,2233.62 r0 bottom value=16.0k
R36 "CRCW06033K30FKEA" 0603S 1822.36,2362.05 r0 bottom value=3.30k
R37 "RC0603FR-079K1L" 0603S 1922.76,2362.05 r0 bottom value=9.10k
R38 "RMCF0603ZT0R00" 0603S 2281.38,2058.78 r180 bottom value=0
R39 "CRCW04025R10JNED" 0402S 2712.13,1751.19 r0 bottom value=5.1
R40 "CRCW06034K30JNEA" 0603S 2405.45,2407.86 r0 bottom value=4.3k
R41 "CRCW0603680RJNEA" 0603S 2408.31,2201.99 r0 bottom value=680
R42 "CRCW04020000Z0ED" 0402S 3256.02,1421.22 r270 top value=0
R43 "CRCW040275R0JNED" 0402S 3085.9,1580.76 r0 bottom value=75
R44 "RMCF0603ZT0R00" 0603S 2033.24,2052.36 r180 bottom value=0
R45 "CRCW04025R10JNED" 0402S 2712.13,1710.63 r0 bottom value=5.1
R46 "CH0402-50RGFPT" 0402S 3082.5,1514.21 r0 bottom value=50
R47 "CH0402-50RGFPT" 0402S 3082.01,1427.25 r0 bottom value=50
R48 "CH0402-50RGFPT" 0402S 3082.45,1470.47 r0 bottom value=50
R49 "RC0603JR-075K1L" 0603S 2335.47,1504.84 r270 bottom value=5.1k
R50 "RC0603JR-075K1L" 0603S 2335.47,1711.04 r90 bottom value=5.1k
R51 "CRCW040210K0JNED" 0402S 3030.82,1818.72 r180 bottom value=10k
R52 "CRCW040210K0JNED" 0402S 3050,1772.19 r0 bottom value=10k
R53 "RC0603JR-075K1L" 0603S 1816.93,1538.11 r0 bottom value=5.1k
R54 "ERJ3EKF1602V" 0603S 1917.32,1538.11 r0 bottom value=16.0k
R55 "CRCW06033K30FKEA" 0603S 1822.36,1666.54 r0 bottom value=3.30k
R56 "RC0603FR-079K1L" 0603S 1922.76,1666.54 r0 bottom value=9.10k
R57 "RMCF0603ZT0R00" 0603S 2268.84,1826.22 r180 bottom value=0
R58 "CRCW06034K30JNEA" 0603S 2414.35,1507.51 r0 bottom value=4.3k
R59 "CRCW0603680RJNEA" 0603S 2417.73,1703.45 r0 bottom value=680
R60 "CRCW04025R10JNED" 0402S 2712.08,1630.68 r0 bottom value=5.1
R61 "RMCF0603ZT0R00" 0603S 2008.21,1864.62 r180 bottom value=0
R62 "CRCW04025R10JNED" 0402S 2712.1,1585.02 r0 bottom value=5.1
R63 "RC0603JR-075K1L" 0603S 2335.47,809.33 r270 bottom value=5.1k
R64 "RC0603JR-075K1L" 0603S 2335.47,1015.53 r90 bottom value=5.1k
R65 "RC0603JR-075K1L" 0603S 1809.05,842.6 r0 bottom value=5.1k
R66 "ERJ3EKF1602V" 0603S 1909.45,842.6 r0 bottom value=16.0k
R67 "CRCW06033K30FKEA" 0603S 1822.36,971.02 r0 bottom value=3.30k
R68 "RC0603FR-079K1L" 0603S 1922.76,971.02 r0 bottom value=9.10k
R69 "RMCF0603ZT0R00" 0603S 2268.84,1130.71 r0 bottom value=0
R70 "CRCW06034K30JNEA" 0603S 2411.41,814.09 r0 bottom value=4.3k
R71 "CRCW0603680RJNEA" 0603S 2405.46,1011.1 r0 bottom value=680
R72 "RMCF0603ZT0R00" 0603S 2002.84,1169.11 r180 bottom value=0
R73 "RMCF0603ZT0R00" 0603S 2813.71,2322.92 r0 bottom value=0
R74 "CRCW06031R00JNEA" 0603S 2833.18,1994.46 r0 bottom value=1.0
R75 "CRCW040210K0JNED" 0402S 2070.47,3181.78 r180 bottom value=10k
R76 "CRCW040210K0JNED" 0402S 2071.17,2482.24 r0 bottom value=10k
R77 "CRCW040210K0JNED" 0402S 2070.44,1775.92 r180 bottom value=10k
R78 "CRCW040210K0JNED" 0402S 2068.74,1073.6 r180 bottom value=10k
R79 "CRCW060347K0FKEA" 0603S 3230.23,2677.25 r90 bottom value=47.0k
R80 "CRCW060347K0FKEA" 0603S 2823.47,2595.56 r180 bottom value=47.0k
R81 "RC0603FR-0791KL" 0603S 3229.46,2578.31 r90 bottom value=91.0k
R82 "RC0603FR-0791KL" 0603S 2847.01,2672.51 r270 bottom value=91.0k
R83 "CRCW060347K0FKEA" 0603S 2808.87,2468.49 r180 bottom value=47.0k
R84 "CRCW060347K0FKEA" 0603S 3230.23,2386.68 r270 bottom value=47.0k
R85 "CRCW040247R0JNED" 0402S 3314.47,1976.46 r0 top value=47
R86 "CRCW04020000Z0ED" 0402S 3294.32,1896.06 r90 top value=0
R87 "CRCW040247R0JNED" 0402S 3314.47,1818.98 r0 top value=47
R88 "CRCW0603820RJNEA" 0603S 2001.97,3405.51 r90 top value=820
R89 "CRCW0603820RJNEA" 0603S 2163.66,3405.51 r90 top value=820
R90 "RC0603FR-0791KL" 0603S 2808.46,2416.11 r0 bottom value=91.0k
R91 "RC0603FR-0791KL" 0603S 3229.46,2485.22 r270 bottom value=91.0k
R92 "CRCW040247R0JNED" 0402S 3310.63,1755.99 r0 top value=47
R93 "CRCW0603820RJNEA" 0603S 2325.35,3405.51 r90 top value=820
R94 "CRCW0603820RJNEA" 0603S 2487.05,3405.51 r90 top value=820
R95 "CRCW040247R0JNED" 0402S 3307.87,1644.2 r0 top value=47
R96 "CRCW040247R0JNED" 0402S 3314.47,1566.43 r0 top value=47
R97 "CRCW040247R0JNED" 0402S 3314.47,1441.03 r0 top value=47
R98 "CRCW040210K0JNED" 0402S 3030.82,2680.38 r0 bottom value=10k
R99 "CRCW040210K0JNED" 0402S 3767.21,1357.13 r90 top value=10k
R100 "RMCF0603ZT0R00" 0603S 3767.67,1563.91 r270 top value=0
R101 "RMCF0603ZT0R00" 0603S 3713.78,1563.91 r90 top value=0
R102 "RMCF0603ZT0R00" 0603S 3767.67,1661.5 r270 top value=0
R103 "RMCF0603ZT0R00" 0603S 3713.78,1661.5 r270 top value=0
R104 "RC0603FR-07470KL" 0603S 2401.09,362.74 r270 bottom value=470k
R105 "RC0603FR-0775KL" 0603S 2475.77,415.91 r180 bottom value=75.0k
R106 "RMCF0603ZT0R00" 0603S 2922.78,801.12 r270 bottom value=0
R107 "CRCW060356K2FKEA" 0603S 3163.43,490.53 r90 bottom value=56.2k
R108 "CRCW0603820RJNEA" 0603S 3251.73,2877.52 r0 bottom value=820
R109 "CRCW060351K0JNEA" 0603S 2905.1,907.78 r0 bottom value=51k
R110 "RT0603BRD07174KL" 0603S 2704.54,904.78 r270 bottom value=174k
R111 "CRCW0603820RJNEA" 0603S 2687.06,2876.82 r0 bottom value=820
R112 "RC0603FR-0743K2L" 0603S 2476.39,469.56 r0 bottom value=43.2k
R113 "RC0603FR-075K62L" 0603S 2480.94,216.45 r90 bottom value=5.62k
R114 "CRCW060310K0FKEA" 0603S 3110.46,391.97 r90 bottom value=10.0k
R115 "RT0603BRD0721K5L" 0603S 2736.31,1001.49 r180 bottom value=21.5k
R116 "RMCF0603ZT0R00" 0603S 3171.75,766.07 r0 bottom value=0
R117 "CRCW0603820RJNEA" 0603S 3059.11,2876.82 r0 bottom value=820
R118 "CRCW060310K0FKEA" 0603S 3106.14,1028.15 r0 bottom value=10.0k
R119 "CRCW060310K0FKEA" 0603S 2988.2,981.88 r90 bottom value=10.0k
R120 "RMCF0603ZT0R00" 0603S 1427.41,2693.64 r90 bottom value=0
R121 "RMCF0603ZT0R00" 0603S 1428.2,1998.02 r90 bottom value=0
R122 "RMCF0603ZT0R00" 0603S 1427.82,1300.92 r90 bottom value=0
R123 "RMCF0603ZT0R00" 0603S 1424.01,604.14 r90 bottom value=0
T1 "PE-67200NL" FP-PE-67200NL_TRANSFORMER_19MM05_14MM35-MFG 943.62,2932.5 r0 top
T2 "PE-67200NL" FP-PE-67200NL_TRANSFORMER_19MM05_14MM35-MFG 943.62,2236.97 r0 top
T3 "PE-67200NL" FP-PE-67200NL_TRANSFORMER_19MM05_14MM35-MFG 943.62,1541.44 r0 top
T4 "PE-67200NL" FP-PE-67200NL_TRANSFORMER_19MM05_14MM35-MFG 943.62,845.91 r0 top
TP1 "5007" Keystone5007 2431.36,2746.79 r0 top
TP2 "5007" Keystone5007 1843.07,2746.79 r0 top
TP3 "5007" Keystone5007 2431.36,2070.52 r0 top
TP4 "5007" Keystone5007 1855.68,2070.52 r0 top
TP5 "5007" Keystone5007 2431.36,1812.81 r0 top
TP6 "5007" Keystone5007 1855.68,1812.81 r0 top
TP7 "5007" Keystone5007 1855.68,1132.15 r0 top
TP8 "5007" Keystone5007 2432.58,1132.15 r0 top
TP9 "5007" Keystone5007 2875.6,3064.09 r180 top
TP10 "5007" Keystone5007 3161.49,3358.1 r0 top
TP11 "5007" Keystone5007 2958.46,3358.1 r0 top
TP12 "5007" Keystone5007 2736.6,3358.1 r0 top
TP13 "5007" Keystone5007 1688.98,312.64 r180 top
TP14 "5007" Keystone5007 2153.66,2011.82 r180 top
TP15 "5007" Keystone5007 2163.66,2700.21 r180 top
TP16 "5007" Keystone5007 3243.15,3064.09 r0 top
TP17 "5007" Keystone5007 2696.87,3064.09 r0 top
TP18 "5007" Keystone5007 3057.06,3064.09 r0 top
U1 "OPA322AIDBVT" DBV0005A_N 1574.6,3014.96 r90 bottom
U2 "OPA322AIDBVT" DBV0005A_N 1574.6,2319.45 r90 bottom
U3 "OPA322AIDBVT" DBV0005A_N 1574.6,1623.94 r90 bottom
U4 "OPA322AIDBVT" DBV0005A_N 1574.6,928.43 r90 bottom
U5 "OPA4322SAIPWR" PW0016A-MFG 2138.62,2996.26 r0 bottom
U6 "OPA4322SAIPWR" PW0016A-MFG 2138.62,2300.75 r0 bottom
U7 "ADS8363SRHBR" RHB0032E_NV 2919.18,1629.72 r0 bottom
U8 "OPA4322SAIPWR" PW0016A-MFG 2138.62,1605.24 r0 bottom
U9 "OPA4322SAIPWR" PW0016A-MFG 2138.62,909.72 r0 bottom
U10 "REF5025IDGKR" DGK0008A_N 2860.55,2154.3 r270 bottom
U11 "OPA4322SAIPWR" PW0016A-MFG 3034.61,2531.58 r0 bottom
U12 "TPS259474ARPWR" RPW0010A-MFG 2503.45,323.37 r270 bottom
U13 "TPS562202DRLR" DRL0006A 2968.9,472.2 r0 bottom
U14 "TPS74501PDRVR" DRV0006A 2797.02,908.01 r0 bottom
U15 "TLV73333PQDBVRQ1" DBV0005A_N 3110.73,915.92 r90 bottom
ZZ1 "This Assembly Note is for PCB labels only" AssemblyNoteLabel 250,4250 r0 top
ZZ2 "These assemblies are ESD sensitive, ESD precautions shall be observed." AssemblyNote 250,4150 r0 top
ZZ3 "These assemblies must be clean and free from flux and all contaminants. Use of no clean flux is not acceptable." AssemblyNote 250,4050 r0 top
ZZ4 "These assemblies must comply with workmanship standards IPC-A-610 Class 2, unless otherwise specified." AssemblyNote 250,3950 r0 top

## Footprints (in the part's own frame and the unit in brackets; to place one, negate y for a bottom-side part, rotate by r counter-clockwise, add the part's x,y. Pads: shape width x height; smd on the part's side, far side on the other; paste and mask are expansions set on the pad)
0402S [mil] "Based on C0402S footprint from PADS legacy"
  rect 15x24 smd: 1(-20,0) 2(20,0)
  body extent -22,-12 22,12, height 24
0603S [mil]
  rect 20x35 smd: 1(-30,0) 2(30,0)
  body extent -34,-19 34,19, height 39
0805 [mm] "0805 from SM-752 data"
  rect 1.3x1.5 smd: 1(-0.85,0) 2(0.85,0)
  silkscreen extent -1.72,-0.97 1.72,0.97, body extent -1.1,-0.72 1.1,0.72, height 1.45
0805_HV [mil] "0805 with 30mil clearance between pads"
  rect 50x63 smd: 1(-40,0) 2(40,0)
  silkscreen extent -74,-40 74,40, body extent -43,-29 43,29, height 57
AssemblyNote [mil] "Assembly Note"
AssemblyNoteLabel [mil] "Assembly Note for PCB Labels"
CE_Mark_5mm [mil] "Minimum text height for CE Mark"
  silkscreen extent -138,-98 138,98
controlCARD-120HSEC [mm] "Pads are not numbered according to Samtec datasheet."
  rect 0.5x2.724 smd: 1(-23.357,-1.678) 2(-23.357,1.722) 3(-22.557,-1.678) 4(-22.557,1.722) 5(-21.757,-1.678) 6(-21.757,1.722) 7(-20.957,-1.678) 8(-20.957,1.722) 9(-20.157,-1.678) 10(-20.157,1.722) 11(-19.357,-1.678) 12(-19.357,1.722) 13(-18.557,-1.678) 14(-18.557,1.722) 15(-17.757,-1.678) 16(-17.757,1.722) 17(-16.957,-1.678) 18(-16.957,1.722) 19(-16.157,-1.678) 20(-16.157,1.722) 21(-15.357,-1.678) 22(-15.357,1.722) 23(-14.557,-1.678) 24(-14.557,1.722) 25(-13.757,-1.678) 26(-13.757,1.722) 27(-12.957,-1.678) 28(-12.957,1.722) 29(-12.157,-1.678) 30(-12.157,1.722) 31(-11.357,-1.678) 32(-11.357,1.722) 33(-10.557,-1.678) 34(-10.557,1.722) 35(-9.757,-1.678) 36(-9.757,1.722) 37(-8.957,-1.678) 38(-8.957,1.722) 39(-8.157,-1.678) 40(-8.157,1.722) 41(-7.357,-1.678) 42(-7.357,1.722) 43(-6.557,-1.678) 44(-6.557,1.722) 45(-5.757,-1.678) 46(-5.757,1.722) 47(-4.957,-1.678) 48(-4.957,1.722) 49(-4.157,-1.678) 50(-4.157,1.722) 51(-3.357,-1.678) 52(-3.357,1.722) 53(-2.557,-1.678) 54(-2.557,1.722) 55(-1.757,-1.678) 56(-1.757,1.722) 57(2.243,-1.678) 58(2.243,1.722) 59(3.043,-1.678) 60(3.043,1.722) 61(3.843,-1.678) 62(3.843,1.722) 63(4.643,-1.678) 64(4.643,1.722) 65(5.443,-1.678) 66(5.443,1.722) 67(6.243,-1.678) 68(6.243,1.722) 69(7.043,-1.678) 70(7.043,1.722) 71(7.843,-1.678) 72(7.843,1.722) 73(8.643,-1.678) 74(8.643,1.722) 75(9.443,-1.678) 76(9.443,1.722) 77(10.243,-1.678) 78(10.243,1.722) 79(11.043,-1.678) 80(11.043,1.722) 81(11.843,-1.678) 82(11.843,1.722) 83(12.643,-1.678) 84(12.643,1.722) 85(13.443,-1.678) 86(13.443,1.722) 87(14.243,-1.678) 88(14.243,1.722) 89(15.043,-1.678) 90(15.043,1.722) 91(15.843,-1.678) 92(15.843,1.722) 93(16.643,-1.678) 94(16.643,1.722) 95(17.443,-1.678) 96(17.443,1.722) 97(18.243,-1.678) 98(18.243,1.722) 99(19.043,-1.678) 100(19.043,1.722) 101(19.843,-1.678) 102(19.843,1.722) 103(20.643,-1.678) 104(20.643,1.722) 105(21.443,-1.678) 106(21.443,1.722) 107(22.243,-1.678) 108(22.243,1.722) 109(23.043,-1.678) 110(23.043,1.722) 111(23.843,-1.678) 112(23.843,1.722) 113(24.643,-1.678) 114(24.643,1.722) 115(25.443,-1.678) 116(25.443,1.722) 117(26.243,-1.678) 118(26.243,1.722) 119(27.043,-1.678) 120(27.043,1.722)
  round 0.025 hole 1.27 unplated mask+0.876: 181(-24.857,0.022) 182(28.543,1.522)
  round 1.348 hole 0.84: 185(-27.207,0.022) 186(30.893,0.022)
  silkscreen extent -32.11,-3.86 35.8,3.9, body extent -31.75,-3.48 35.3,3.52, height 12.35
DBV0005A_N [mm] "SOT23, 5-Leads, Body 2.9x1.6mm, Pitch 0.95mm, Lead Span 2.8mm, IPC Medium Density"
  rrect17% 1x0.6 smd: 1(-1.375,0.95) 2(-1.375,0) 3(-1.375,-0.95) 4(1.375,-0.95) 5(1.375,0.95)
  silkscreen extent -0.25,-1.55 0.25,1.55, body extent -1.42,-1.46 1.42,1.46, height 1.09
DGK0008A_N [mm] "TSOP, 8-Leads, Body 3x3mm, Pitch 0.65mm, IPC Medium Density"
  oval 1.35x0.45 smd: 1(-2.225,0.975) 2(-2.225,0.325) 3(-2.225,-0.325) 4(-2.225,-0.975) 5(2.225,-0.975) 6(2.225,-0.325) 7(2.225,0.325) 8(2.225,0.975)
  silkscreen extent -2.75,-1.55 0.95,1.55, body extent -2.45,-1.5 2.45,1.5, height 0.96
DRL0006A [mm] "SOTFL, 6-Flat Leads, Body 1.2x1.6x0.6mm, Pitch 0.5mm, TI recommended"
  rrect33% 0.67x0.3 smd: 1(-0.74,0.5) 2(-0.74,0) 3(-0.74,-0.5) 4(0.74,-0.5) 5(0.74,0) 6(0.74,0.5)
  silkscreen extent -0.9,-0.95 0.5,0.95, body extent -0.8,-0.8 0.8,0.8, height 0.61
DRV0006A [mm] "SON, 6-Leads, Body 2x2mm, Pitch 0.65mm, Thermal Pad 1.6x1mm, TI Recommended"
  rrect33% 0.45x0.3 smd: 1(-0.975,0.65) 2(-0.975,0) 3(-0.975,-0.65) 4(0.975,-0.65) 5(0.975,0) 6(0.975,0.65)
  rrect14% 1x0.7 on Bottom Paste: 7(0,-0.45) 7(0,0.45)
  rrect10% 1x1.6 smd paste-0.5: 7(0,0)
  silkscreen extent -1.05,-1.2 1.05,1.2, body extent -1.05,-1.05 1.05,1.05, height 0.81
FCC_disclaimer [mil]
Fiducial10-30 [mm]
  round 1 smd mask+1: 1(0,0)
  Top Layer keep-out circle w1.678: c0,0 r0.75
FP-PE-67200NL_TRANSFORMER_19MM05_14MM35-MFG [mm]
  rrect4% 2.35x2.35 hole 1.55 paste-1000 mask+0: 1(-7.62,5.08)
  round 2.35 hole 1.55 paste-1000 mask+0: 2(-7.62,-5.08)
  round 1.9 hole 1.25 paste-1000 mask+0: 3(7.62,5.08) 4(7.62,-5.08)
  silkscreen extent -10.12,-7.17 9.52,7.18, body extent -9.62,-7.27 9.62,7.27, height 0.25
IEC_HighVoltage_Small [mil]
  silkscreen extent -107,-88 107,97
IEC_HotSurface_Small [mil]
  silkscreen extent -107,-93 107,92
Keystone5007 [mil] "Keystone Compact loops"
  round 87 hole 63: 1(0,0)
  silkscreen extent -70,-70 70,70, body extent -63,-63 62,63, height 225
Keystone_1902C [mil] "Hex Standoff, 4-40 threaded, nylon"
  round 1 on Mech4: 0(0,0)
  body extent -145,-126 146,126, height 501
Label_650x200 [mil] "Thermal Transfer Label"
  round 1 on Mech13: 0(0,0)
  silkscreen extent -325,-100 325,100, body extent -325,-100 325,100, height 1
Molex_0022284043 [mm] "Header, 2.54mm, 4x1, TH"
  rect 1.55x1.55 hole 1.02: 1(-3.81,0)
  round 1.55 hole 1.02: 2(-1.27,0) 3(1.27,0) 4(3.81,0)
  silkscreen extent -5.08,-1.24 5.08,1.5, body extent -5.08,-1.24 5.08,1.24, height 8.4
"NY PMS 440 0025 PH" [mm] "4-40 nylon screw and mounting hole"
  round 8 hole 3.2: 1(0,0)
  body extent -3.3,-3.3 3.3,3.3, height 2.69
Phoenix_1714955 [mm] "Terminal Block, 2x1, 6.35mm, TH"
  rect 1.8x1.8 hole 1.3: 1(-3.175,0)
  round 1.8 hole 1.3: 2(3.175,0)
  silkscreen extent -6.7,-7.9 6.35,4.6, body extent -6.92,-7.9 6.35,4.6, height 21.5
PW0016A-MFG [mm]
  rrect22% 1.5x0.45 smd paste+0 mask+0: 1(-2.9,2.275) 2(-2.9,1.625) 3(-2.9,0.975) 4(-2.9,0.325) 5(-2.9,-0.325) 6(-2.9,-0.975) 7(-2.9,-1.625) 8(-2.9,-2.275) 9(2.9,-2.275) 10(2.9,-1.625) 11(2.9,-0.975) 12(2.9,-0.325) 13(2.9,0.325) 14(2.9,0.975) 15(2.9,1.625) 16(2.9,2.275)
  silkscreen extent -4.37,-2.55 1.78,2.55, body extent -3.2,-2.5 3.2,2.5, height 1.2
RHB0032E_NV [mm] "QFN, 32-Leads, Body 5x5mm, Pitch 0.5mm, Thermal Pad 3.45x3.45mm, TI Recommended"
  rrect40% 0.6x0.25 smd: 1(-2.4,1.75) 2(-2.4,1.25) 3(-2.4,0.75) 4(-2.4,0.25) 5(-2.4,-0.25) 6(-2.4,-0.75) 7(-2.4,-1.25) 8(-2.4,-1.75) 17(2.4,-1.75) 18(2.4,-1.25) 19(2.4,-0.75) 20(2.4,-0.25) 21(2.4,0.25) 22(2.4,0.75) 23(2.4,1.25) 24(2.4,1.75)
  rrect40% 0.25x0.6 smd: 9(-1.75,-2.4) 10(-1.25,-2.4) 11(-0.75,-2.4) 12(-0.25,-2.4) 13(0.25,-2.4) 14(0.75,-2.4) 15(1.25,-2.4) 16(1.75,-2.4) 25(1.75,2.4) 26(1.25,2.4) 27(0.75,2.4) 28(0.25,2.4) 29(-0.25,2.4) 30(-0.75,2.4) 31(-1.25,2.4) 32(-1.75,2.4)
  rrect3% 3.45x3.45 smd paste-1.725: 33(0,0)
  rrect7% 1.49x1.49 on Bottom Paste: ""(-0.845,-0.845) ""(-0.845,0.845) ""(0.845,-0.845) ""(0.845,0.845)
  silkscreen extent -2.72,-2.73 2.72,2.73, body extent -2.57,-2.57 2.58,2.58, height 1.01
RPW0010A-MFG [mm]
  round 0.27 smd paste-1000 mask+0: 1(-1.05,0.7) 10(0.75,0.7)
  rrect40% 0.6x0.25 smd paste+0 mask+0: 2(-0.9,0.225) 3(-0.9,-0.225) 8(0.9,-0.225) 9(0.9,0.225)
  round 0.255 smd paste-1000 mask+0: 4(-0.75,-0.75) 7(0.75,-0.75)
  rrect33% 0.3x2.4 smd paste-1000 mask+0: 5(-0.25,0) 6(0.25,0)
  Top Layer region: 0.85,0.85 0.85,1.15 0.846,1.169 0.835,1.185 0.819,1.196 0.8,1.2 0.8,1.2 0.65,1.2 0.631,1.196 0.615,1.185 0.604,1.169 0.6,1.15 0.6,1.15 0.6,0.6 0.604,0.581 0.615,0.565 0.631,0.554 0.65,0.55 0.65,0.55 1.15,0.55 1.169,0.554 1.185,0.565 1.196,0.581 1.2,0.6 1.2,0.6 1.2,0.8 1.196,0.819 1.185,0.835 1.169,0.846 1.15,0.85 1.15,0.85
  Top Layer region: 0.85,-0.85 0.85,-1.15 0.846,-1.169 0.835,-1.185 0.819,-1.196 0.8,-1.2 0.8,-1.2 0.65,-1.2 0.631,-1.196 0.615,-1.185 0.604,-1.169 0.6,-1.15 0.6,-1.15 0.6,-0.6 0.604,-0.581 0.615,-0.565 0.631,-0.554 0.65,-0.55 0.65,-0.55 1.15,-0.55 1.169,-0.554 1.185,-0.565 1.196,-0.581 1.2,-0.6 1.2,-0.6 1.2,-0.8 1.196,-0.819 1.185,-0.835 1.169,-0.846 1.15,-0.85 1.15,-0.85
  Top Layer region: -0.85,-0.85 -0.85,-1.15 -0.846,-1.169 -0.835,-1.185 -0.819,-1.196 -0.8,-1.2 -0.8,-1.2 -0.65,-1.2 -0.631,-1.196 -0.615,-1.185 -0.604,-1.169 -0.6,-1.15 -0.6,-1.15 -0.6,-0.6 -0.604,-0.581 -0.615,-0.565 -0.631,-0.554 -0.65,-0.55 -0.65,-0.55 -1.15,-0.55 -1.169,-0.554 -1.185,-0.565 -1.196,-0.581 -1.2,-0.6 -1.2,-0.6 -1.2,-0.8 -1.196,-0.819 -1.185,-0.835 -1.169,-0.846 -1.15,-0.85 -1.15,-0.85
  Top Layer region: -0.85,0.85 -0.85,1.15 -0.843,1.175 -0.825,1.193 -0.8,1.2 -0.8,1.2 -0.65,1.2 -0.631,1.196 -0.615,1.185 -0.604,1.169 -0.6,1.15 -0.6,1.15 -0.6,0.6 -0.604,0.581 -0.615,0.565 -0.631,0.554 -0.65,0.55 -0.65,0.55 -1.15,0.55 -1.169,0.554 -1.185,0.565 -1.196,0.581 -1.2,0.6 -1.2,0.6 -1.2,0.8 -1.193,0.825 -1.175,0.843 -1.15,0.85 -1.15,0.85
  silkscreen extent -1.87,-1.58 1.05,1.58, body extent -1,-1 1,1, height 1
SOD-123 [mm] "On Semi recommended land pattern"
  rect 0.915x1.22 smd: 1(-1.637,0) 2(1.637,0)
  silkscreen extent -2.74,-1.17 2.03,1.17, body extent -1.93,-0.9 1.93,0.9, height 1.35
SOT-323 [mm] "Diodes Inc recommended land pattern.  2016-02-24"
  rrect21% 0.6x0.47 smd: 1(-0.95,0.65) 2(-0.95,-0.65) 3(0.95,0)
  silkscreen extent -1.14,-1.22 0.77,1.22, body extent -1.13,-1.13 1.12,1.12, height 1.13
TI_Stacked_Overlay_Small [mil]
  silkscreen extent -418,-98 418,98
WE-LHMI_7050 [mm] "Wurth"
  rect 2.95x3.5 smd: 1(-2.725,0) 2(2.725,0)
  silkscreen extent -3.55,-3.55 3.55,3.55, body extent -3.8,-3.45 3.8,3.45, height 5
WEEE_Minimum [mil] "WEEElie bin"
  silkscreen extent -95,-172 99,104
WL-SMCD-0603 [mm] "SMD, 2-Leads, Body 1.6x0.8mm"
  rrect13% 0.8x0.75 smd: 1(-0.8,0) 2(0.8,0)
  body extent -0.8,-0.4 0.8,0.4, height 0.4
